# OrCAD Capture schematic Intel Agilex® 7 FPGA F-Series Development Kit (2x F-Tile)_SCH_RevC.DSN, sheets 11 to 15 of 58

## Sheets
11 PG11 AGX SDM: size C
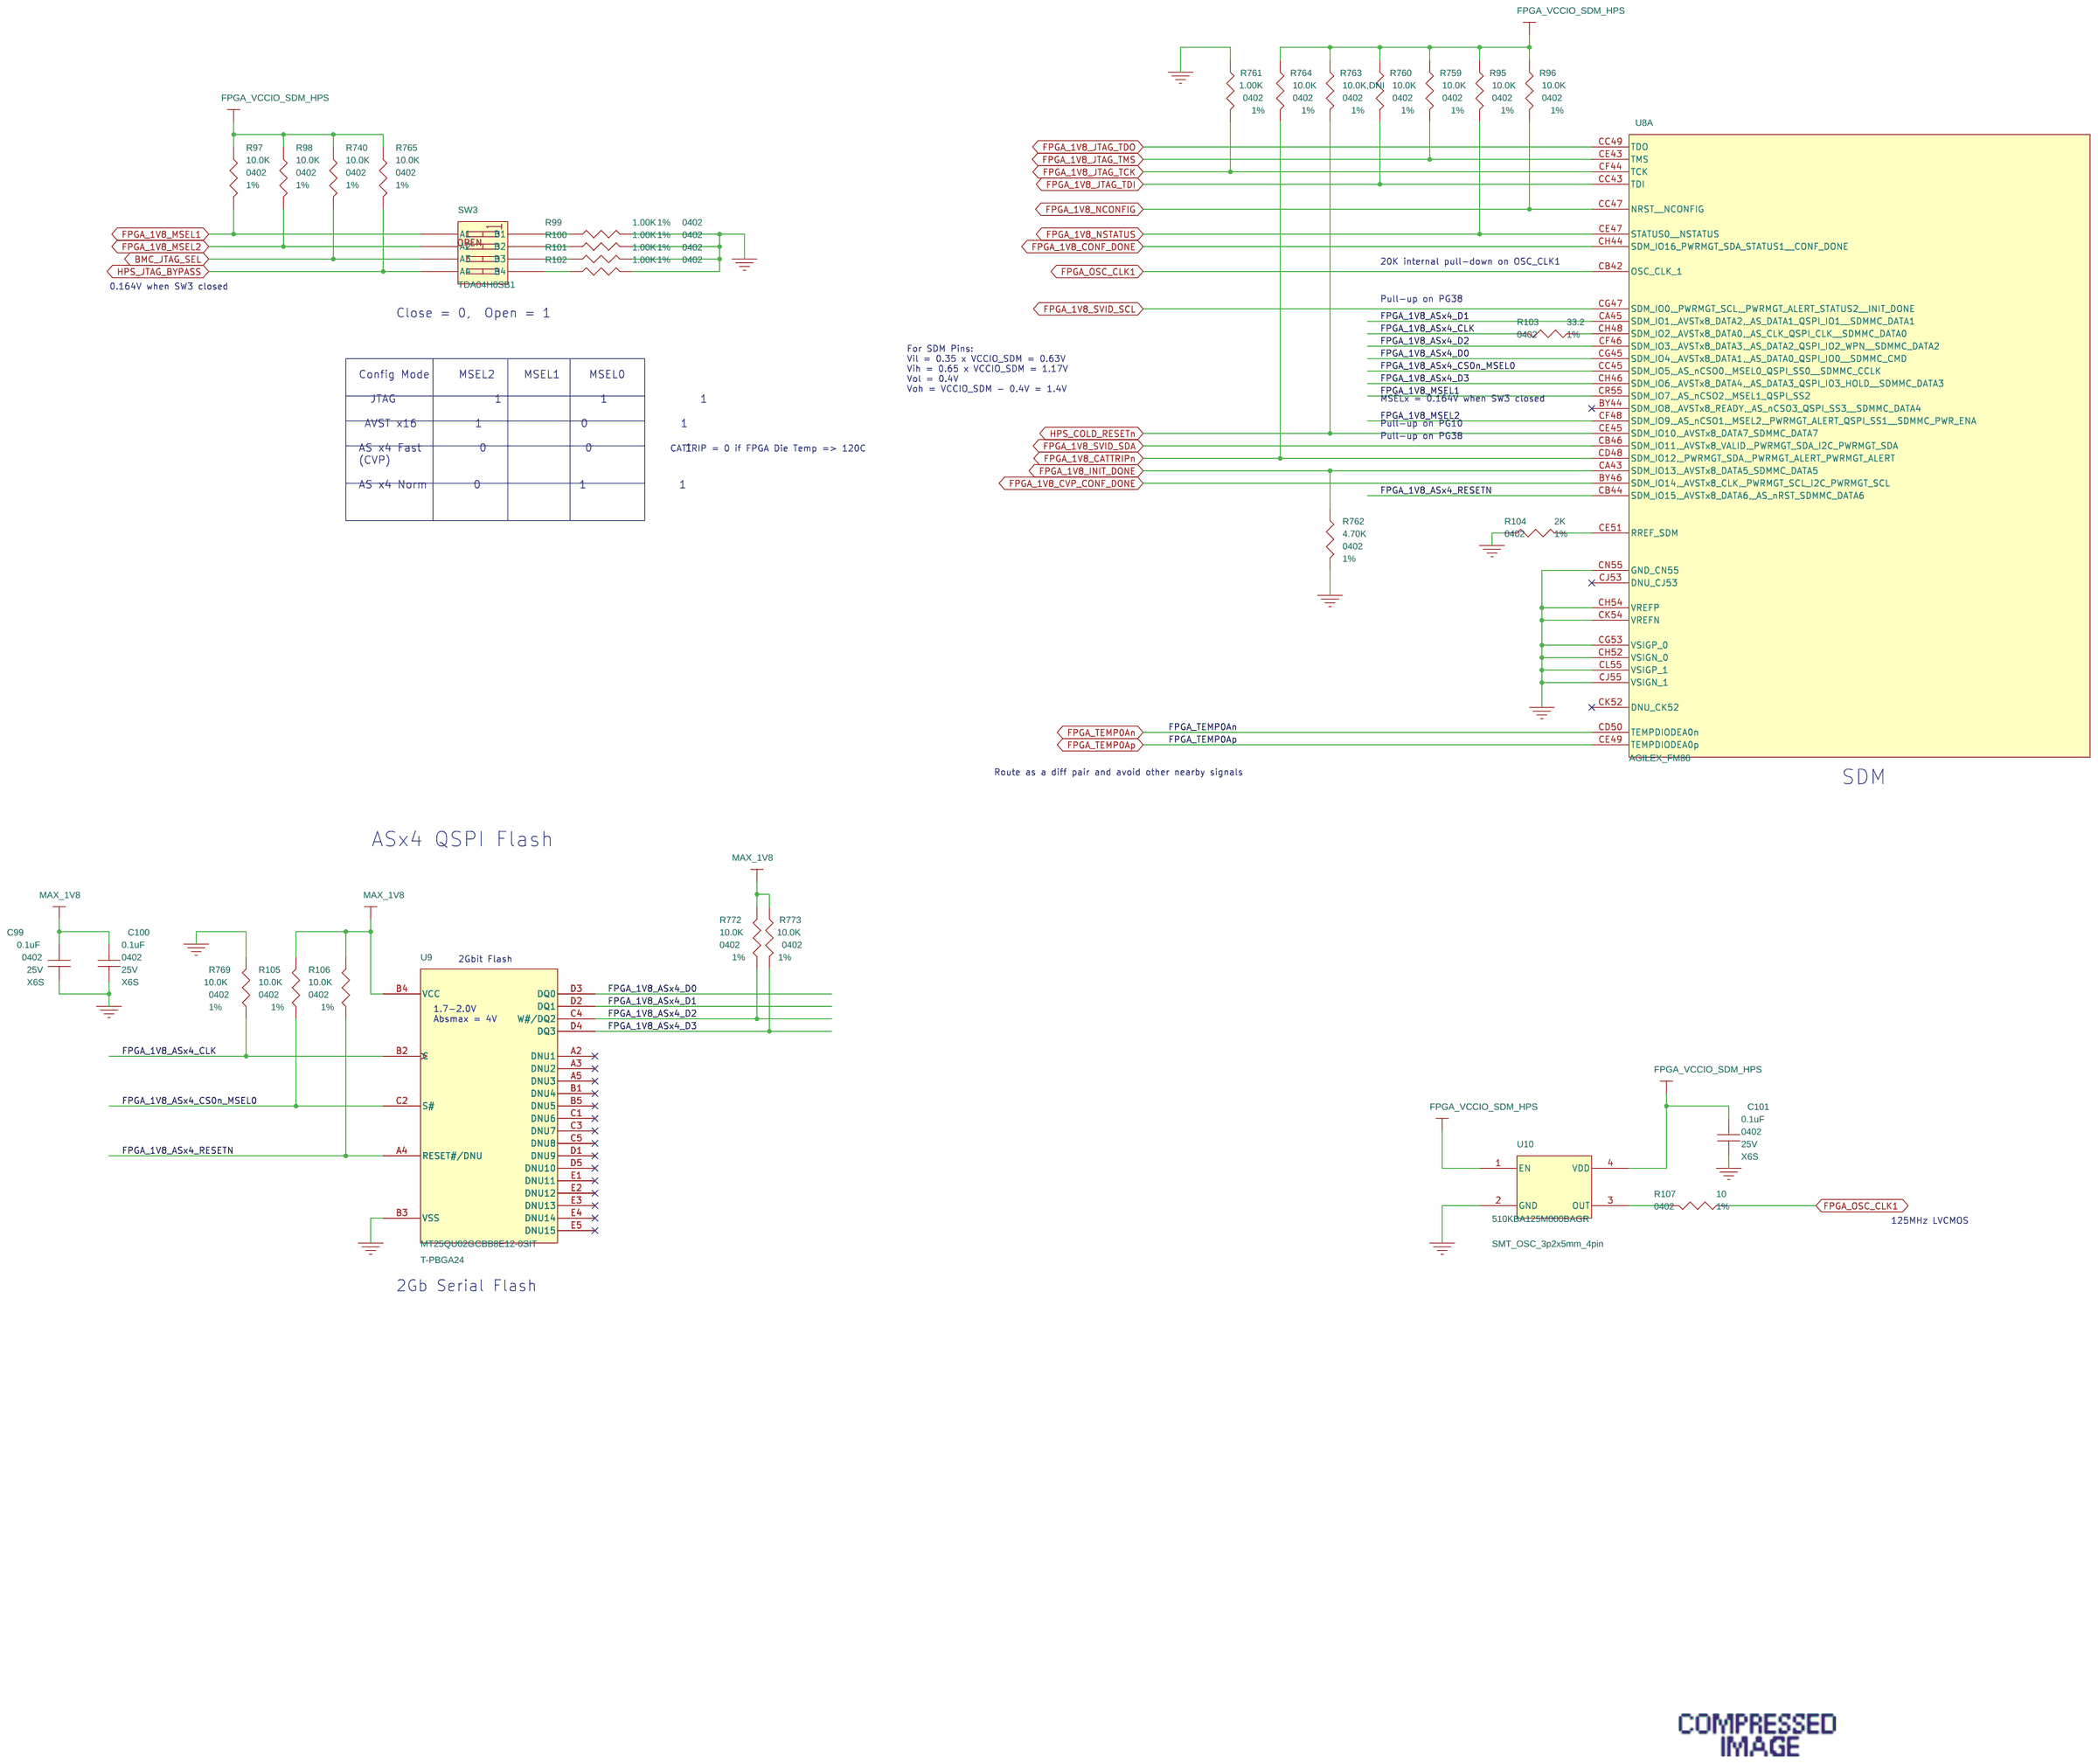
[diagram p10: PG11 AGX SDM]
12 PG12 AGX BANK 2C - DDR4 DIMM1: size C
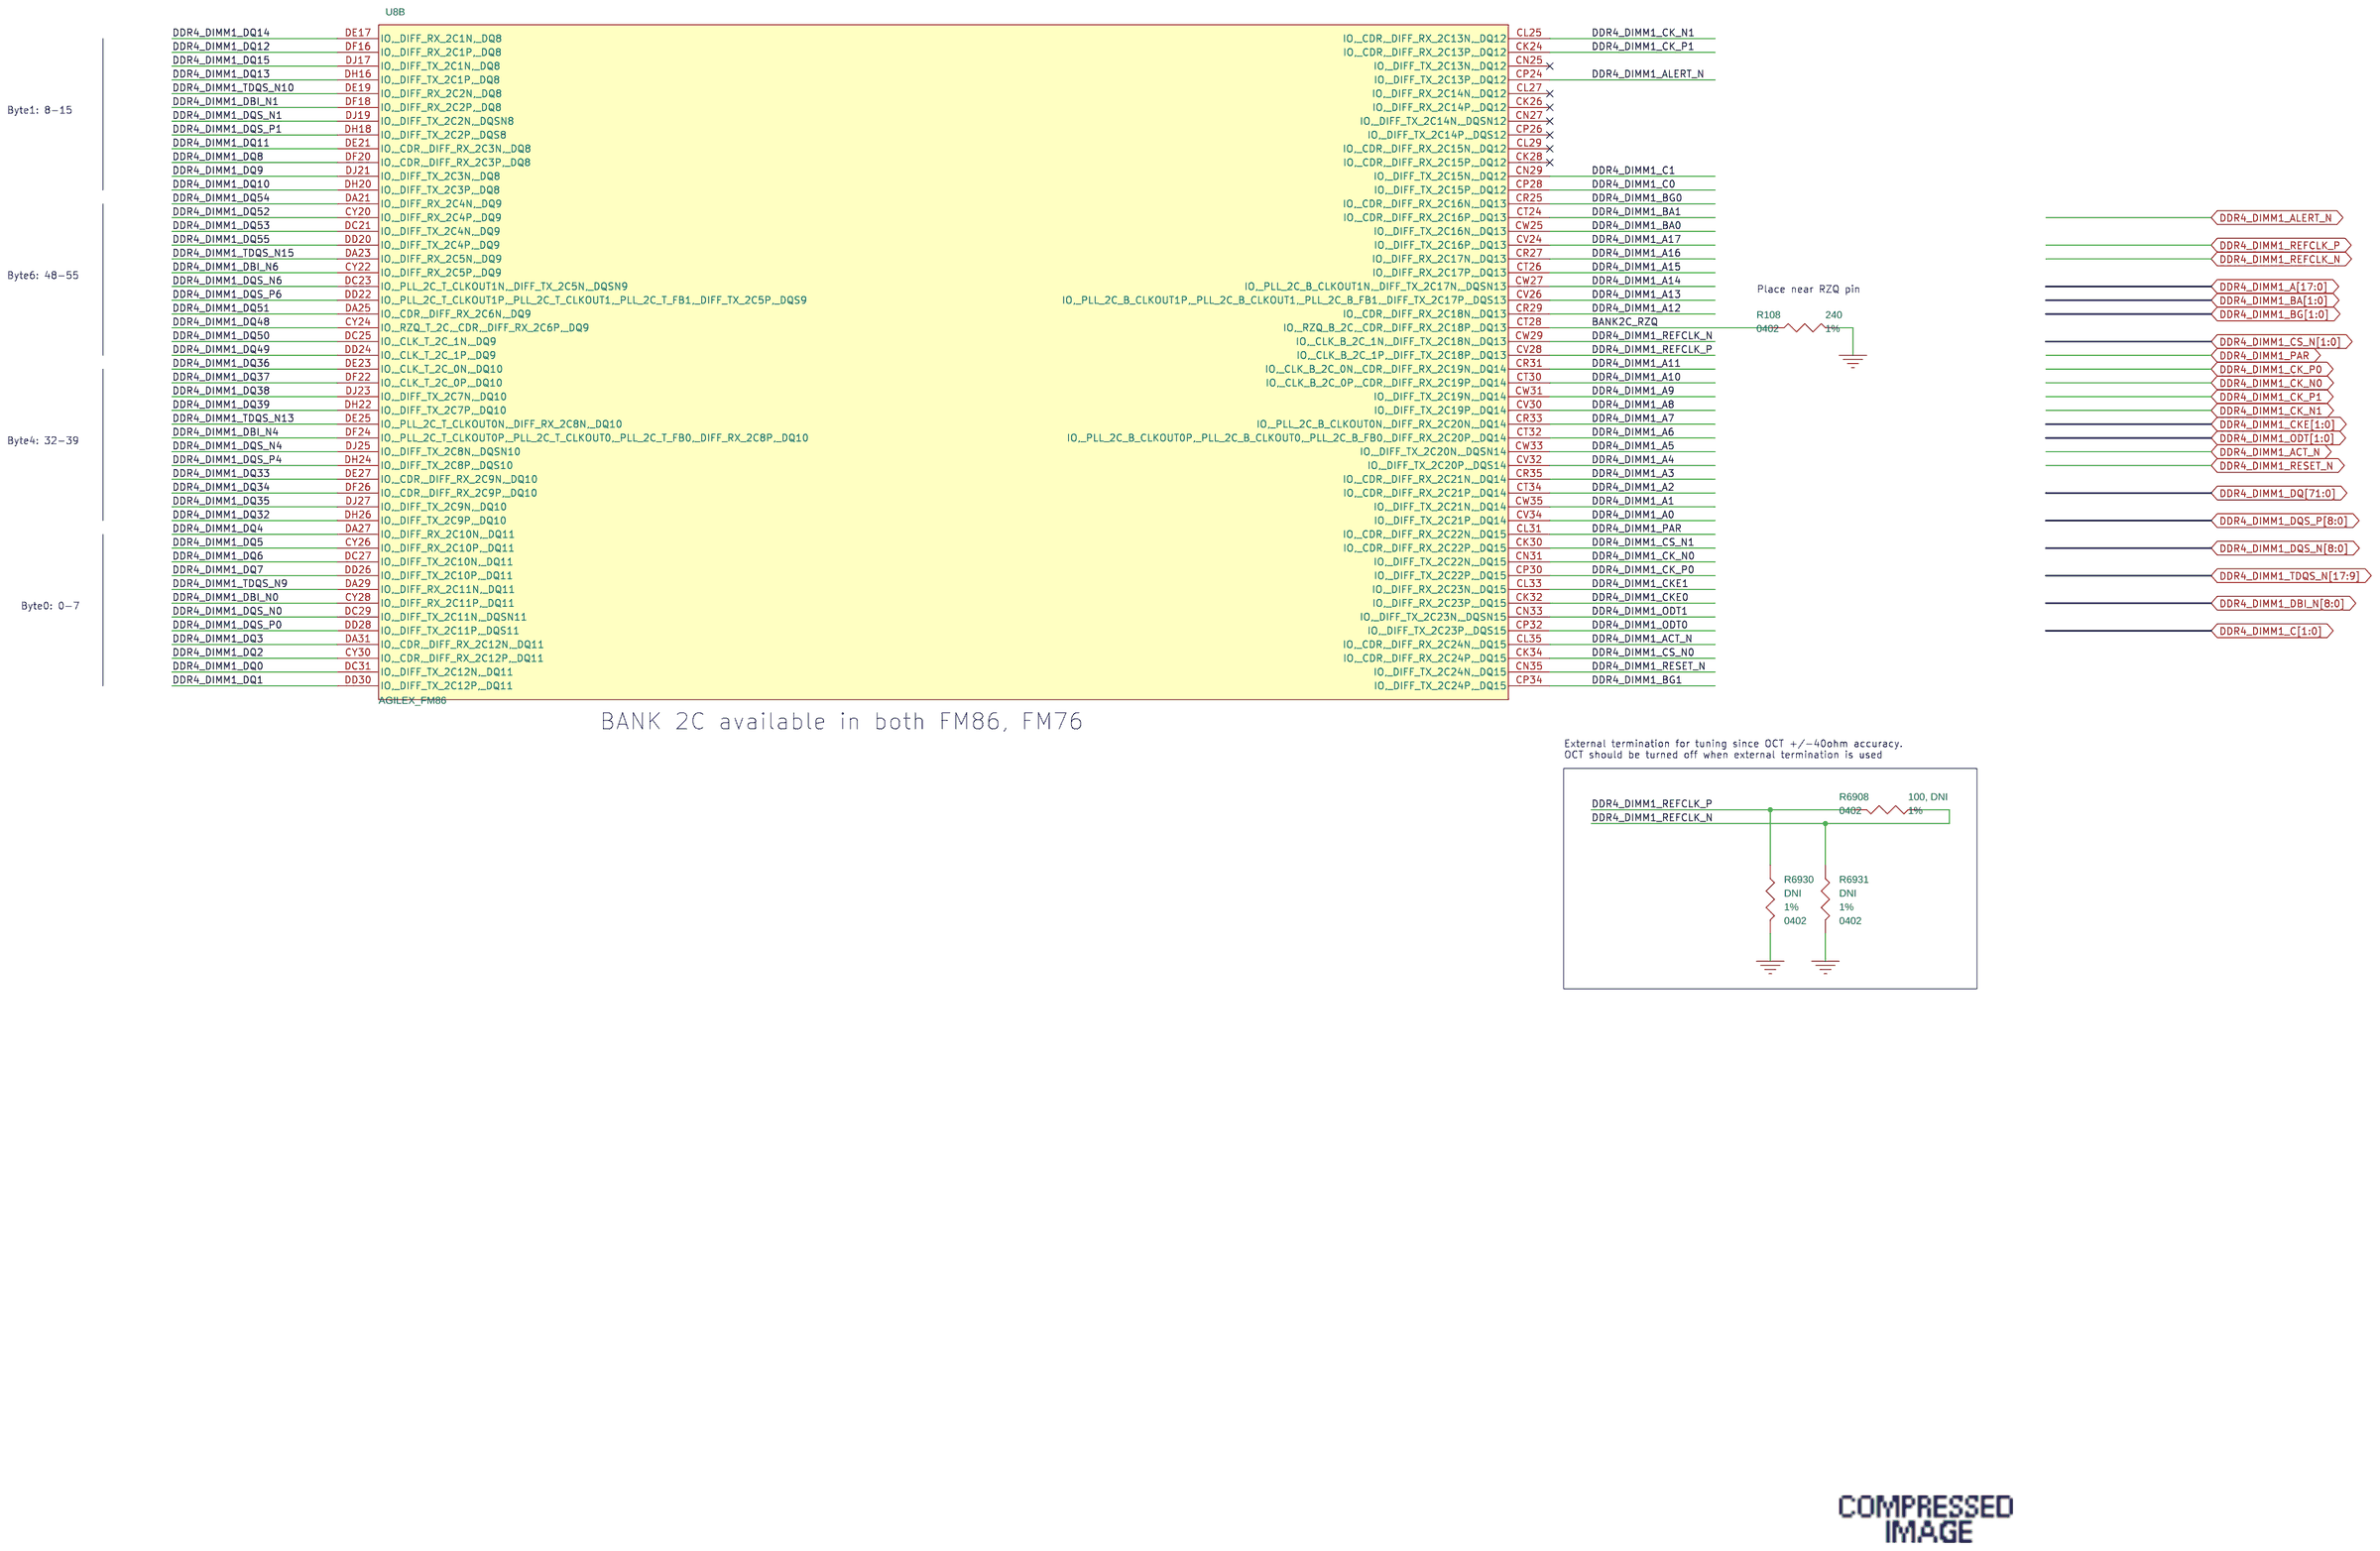
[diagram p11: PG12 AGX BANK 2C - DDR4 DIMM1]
13 PG13 AGX BANK 2D - DDR4 DIMM1: size C
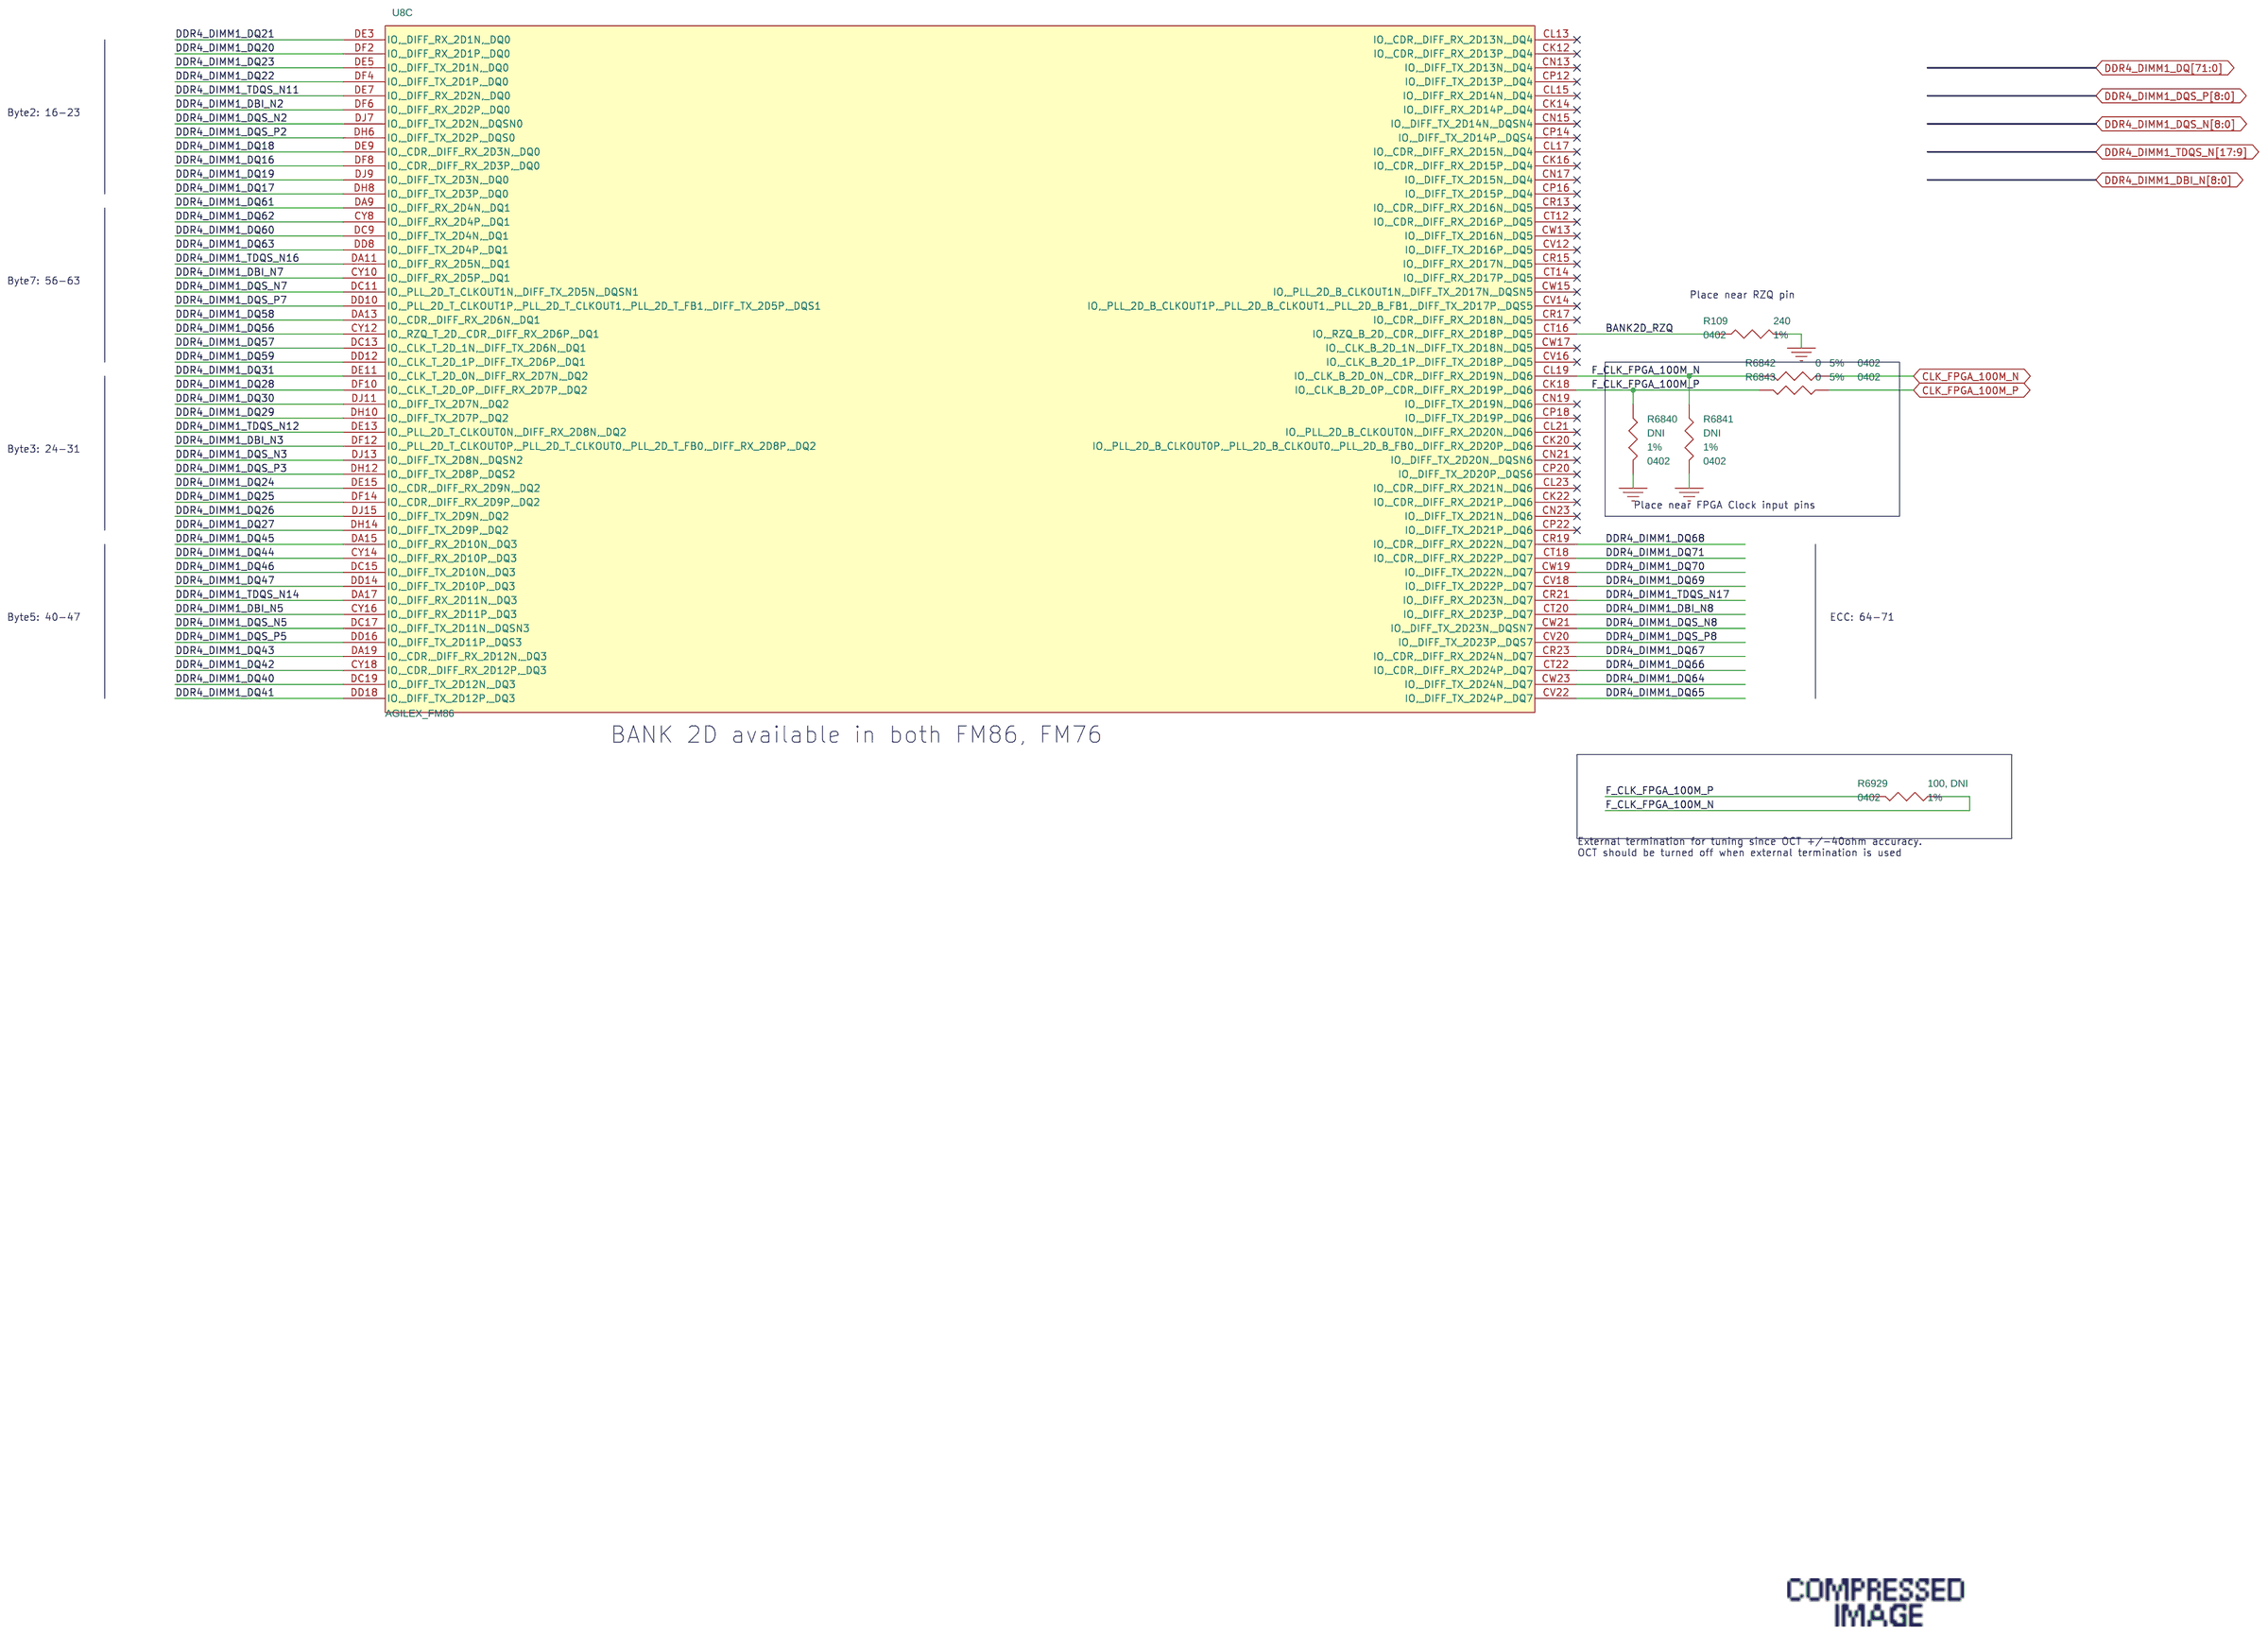
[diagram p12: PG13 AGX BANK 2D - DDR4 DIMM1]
14 PG14 AGX BANK 2E - DDR4 DIMM2: size C
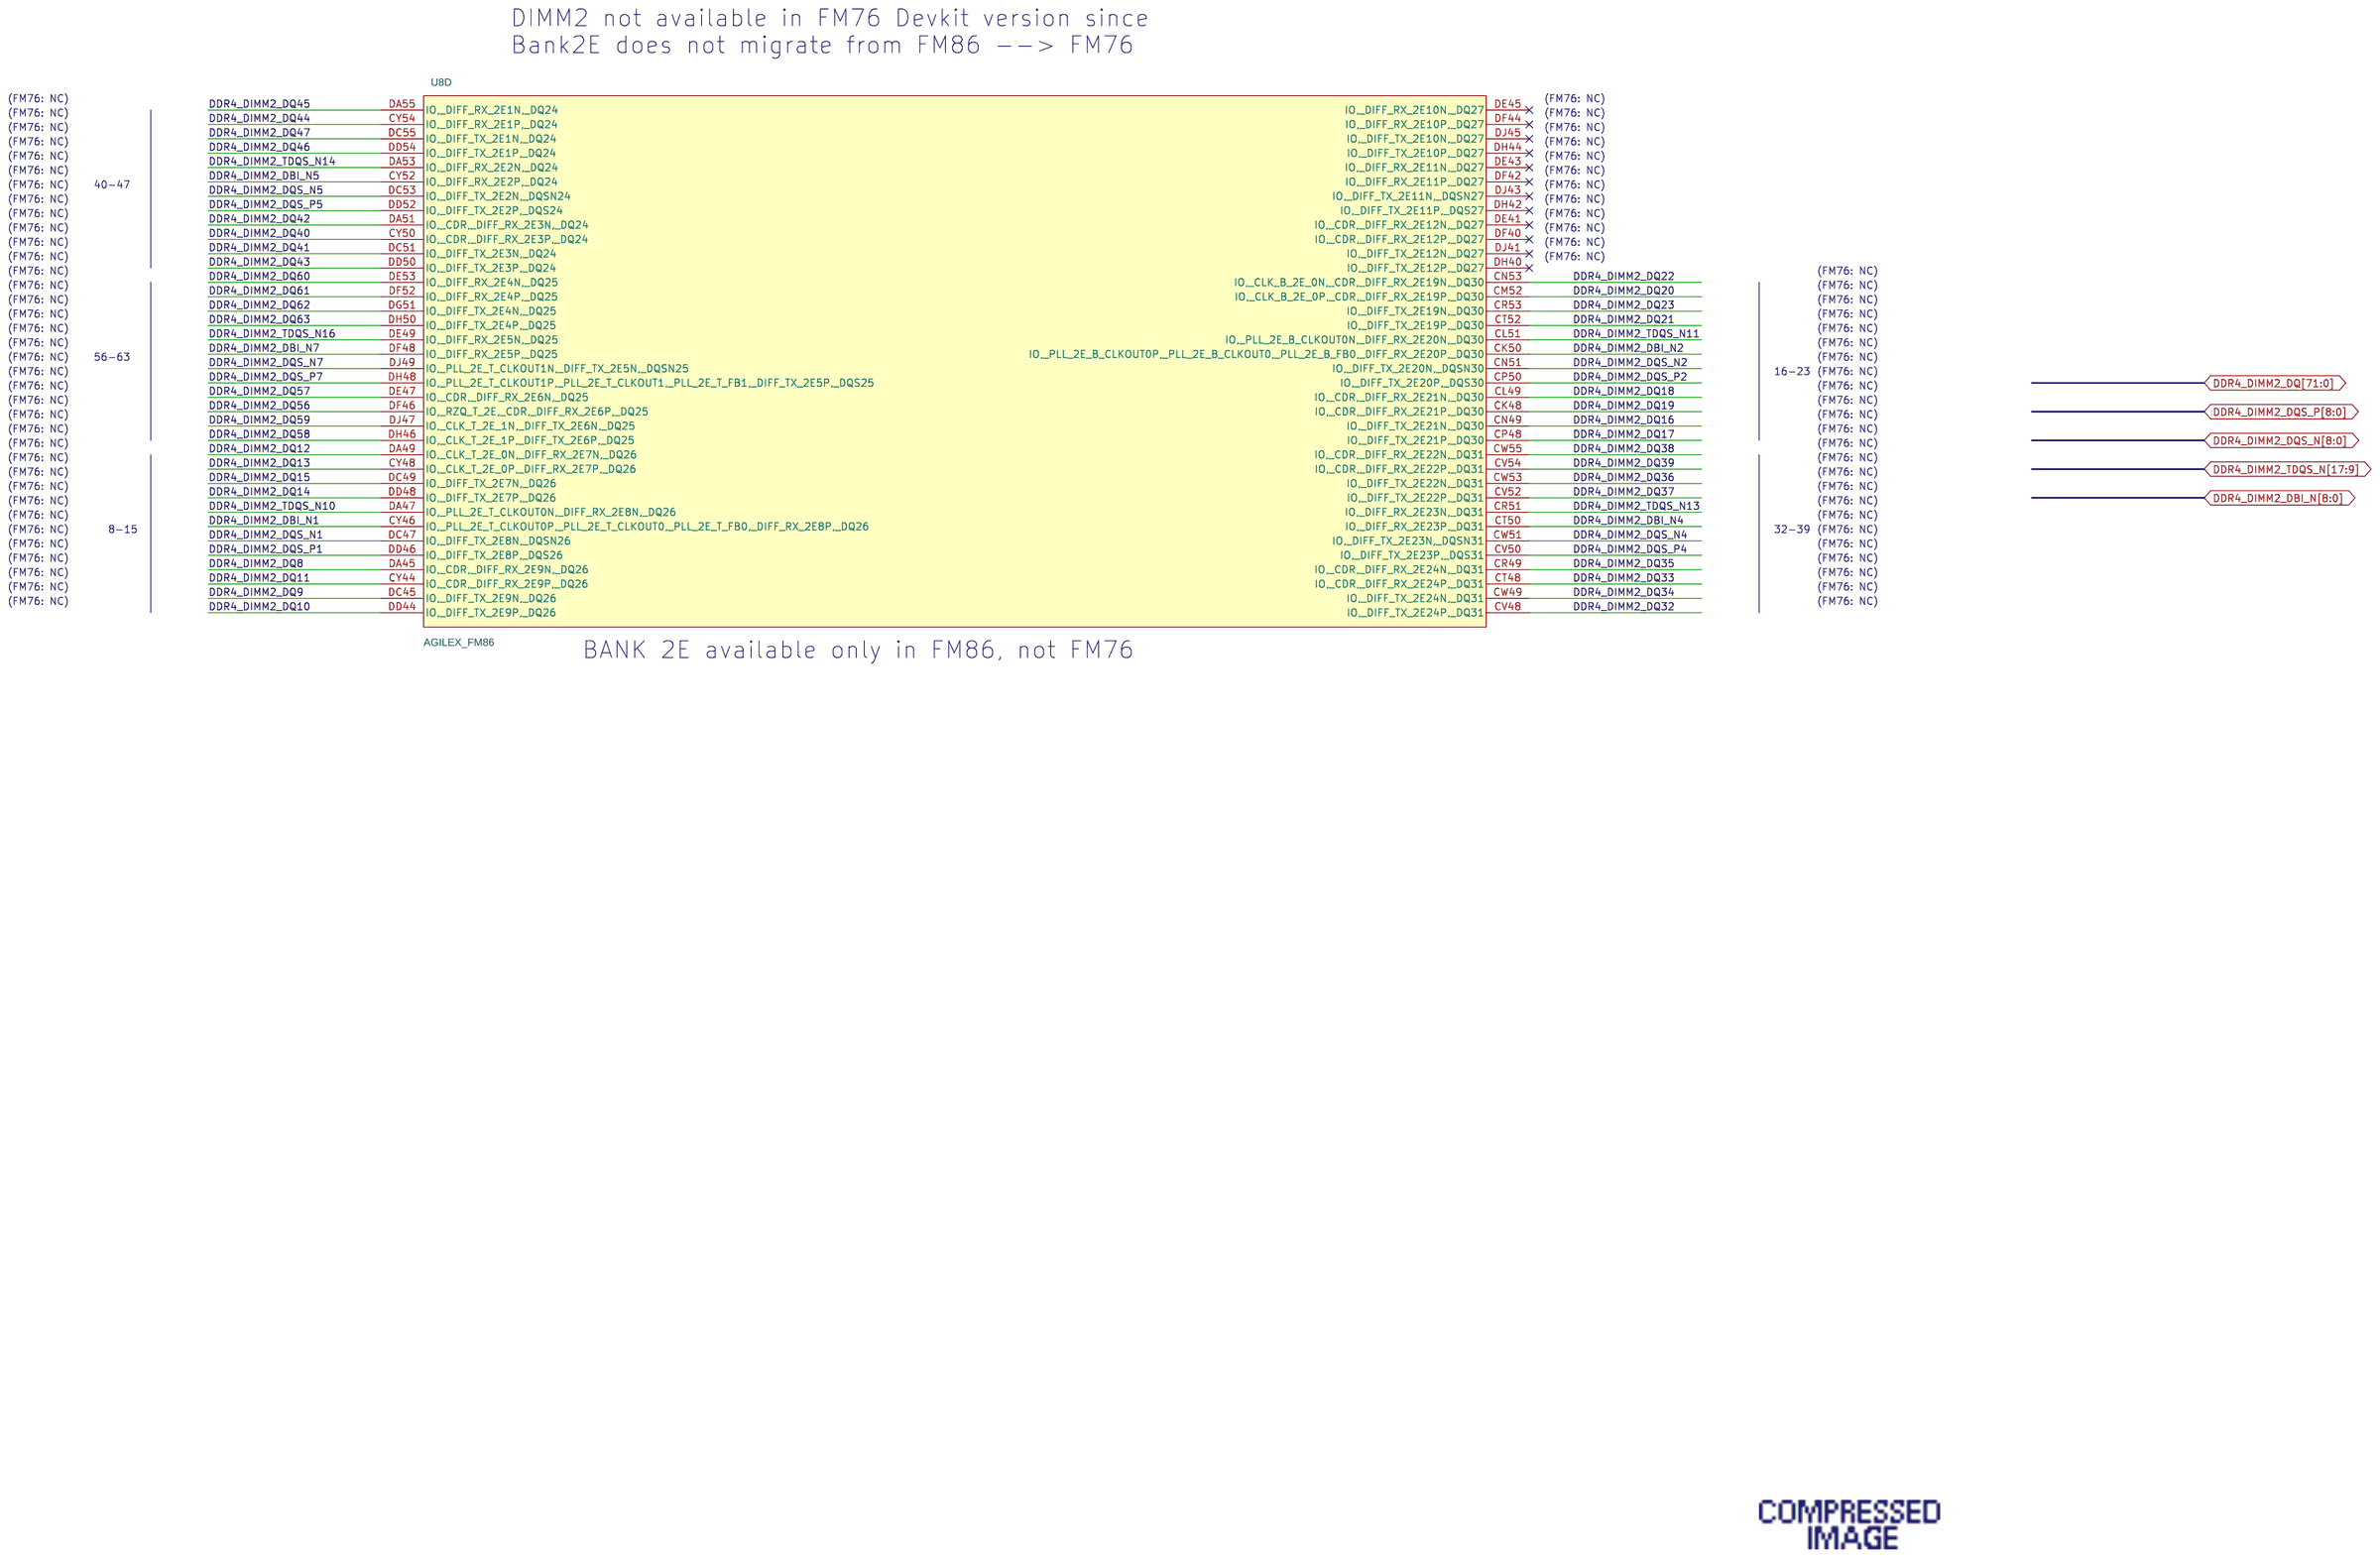
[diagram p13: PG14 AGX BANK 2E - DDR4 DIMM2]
15 PG15 AGX BANK 2F - DDR4 DIMM2: size C
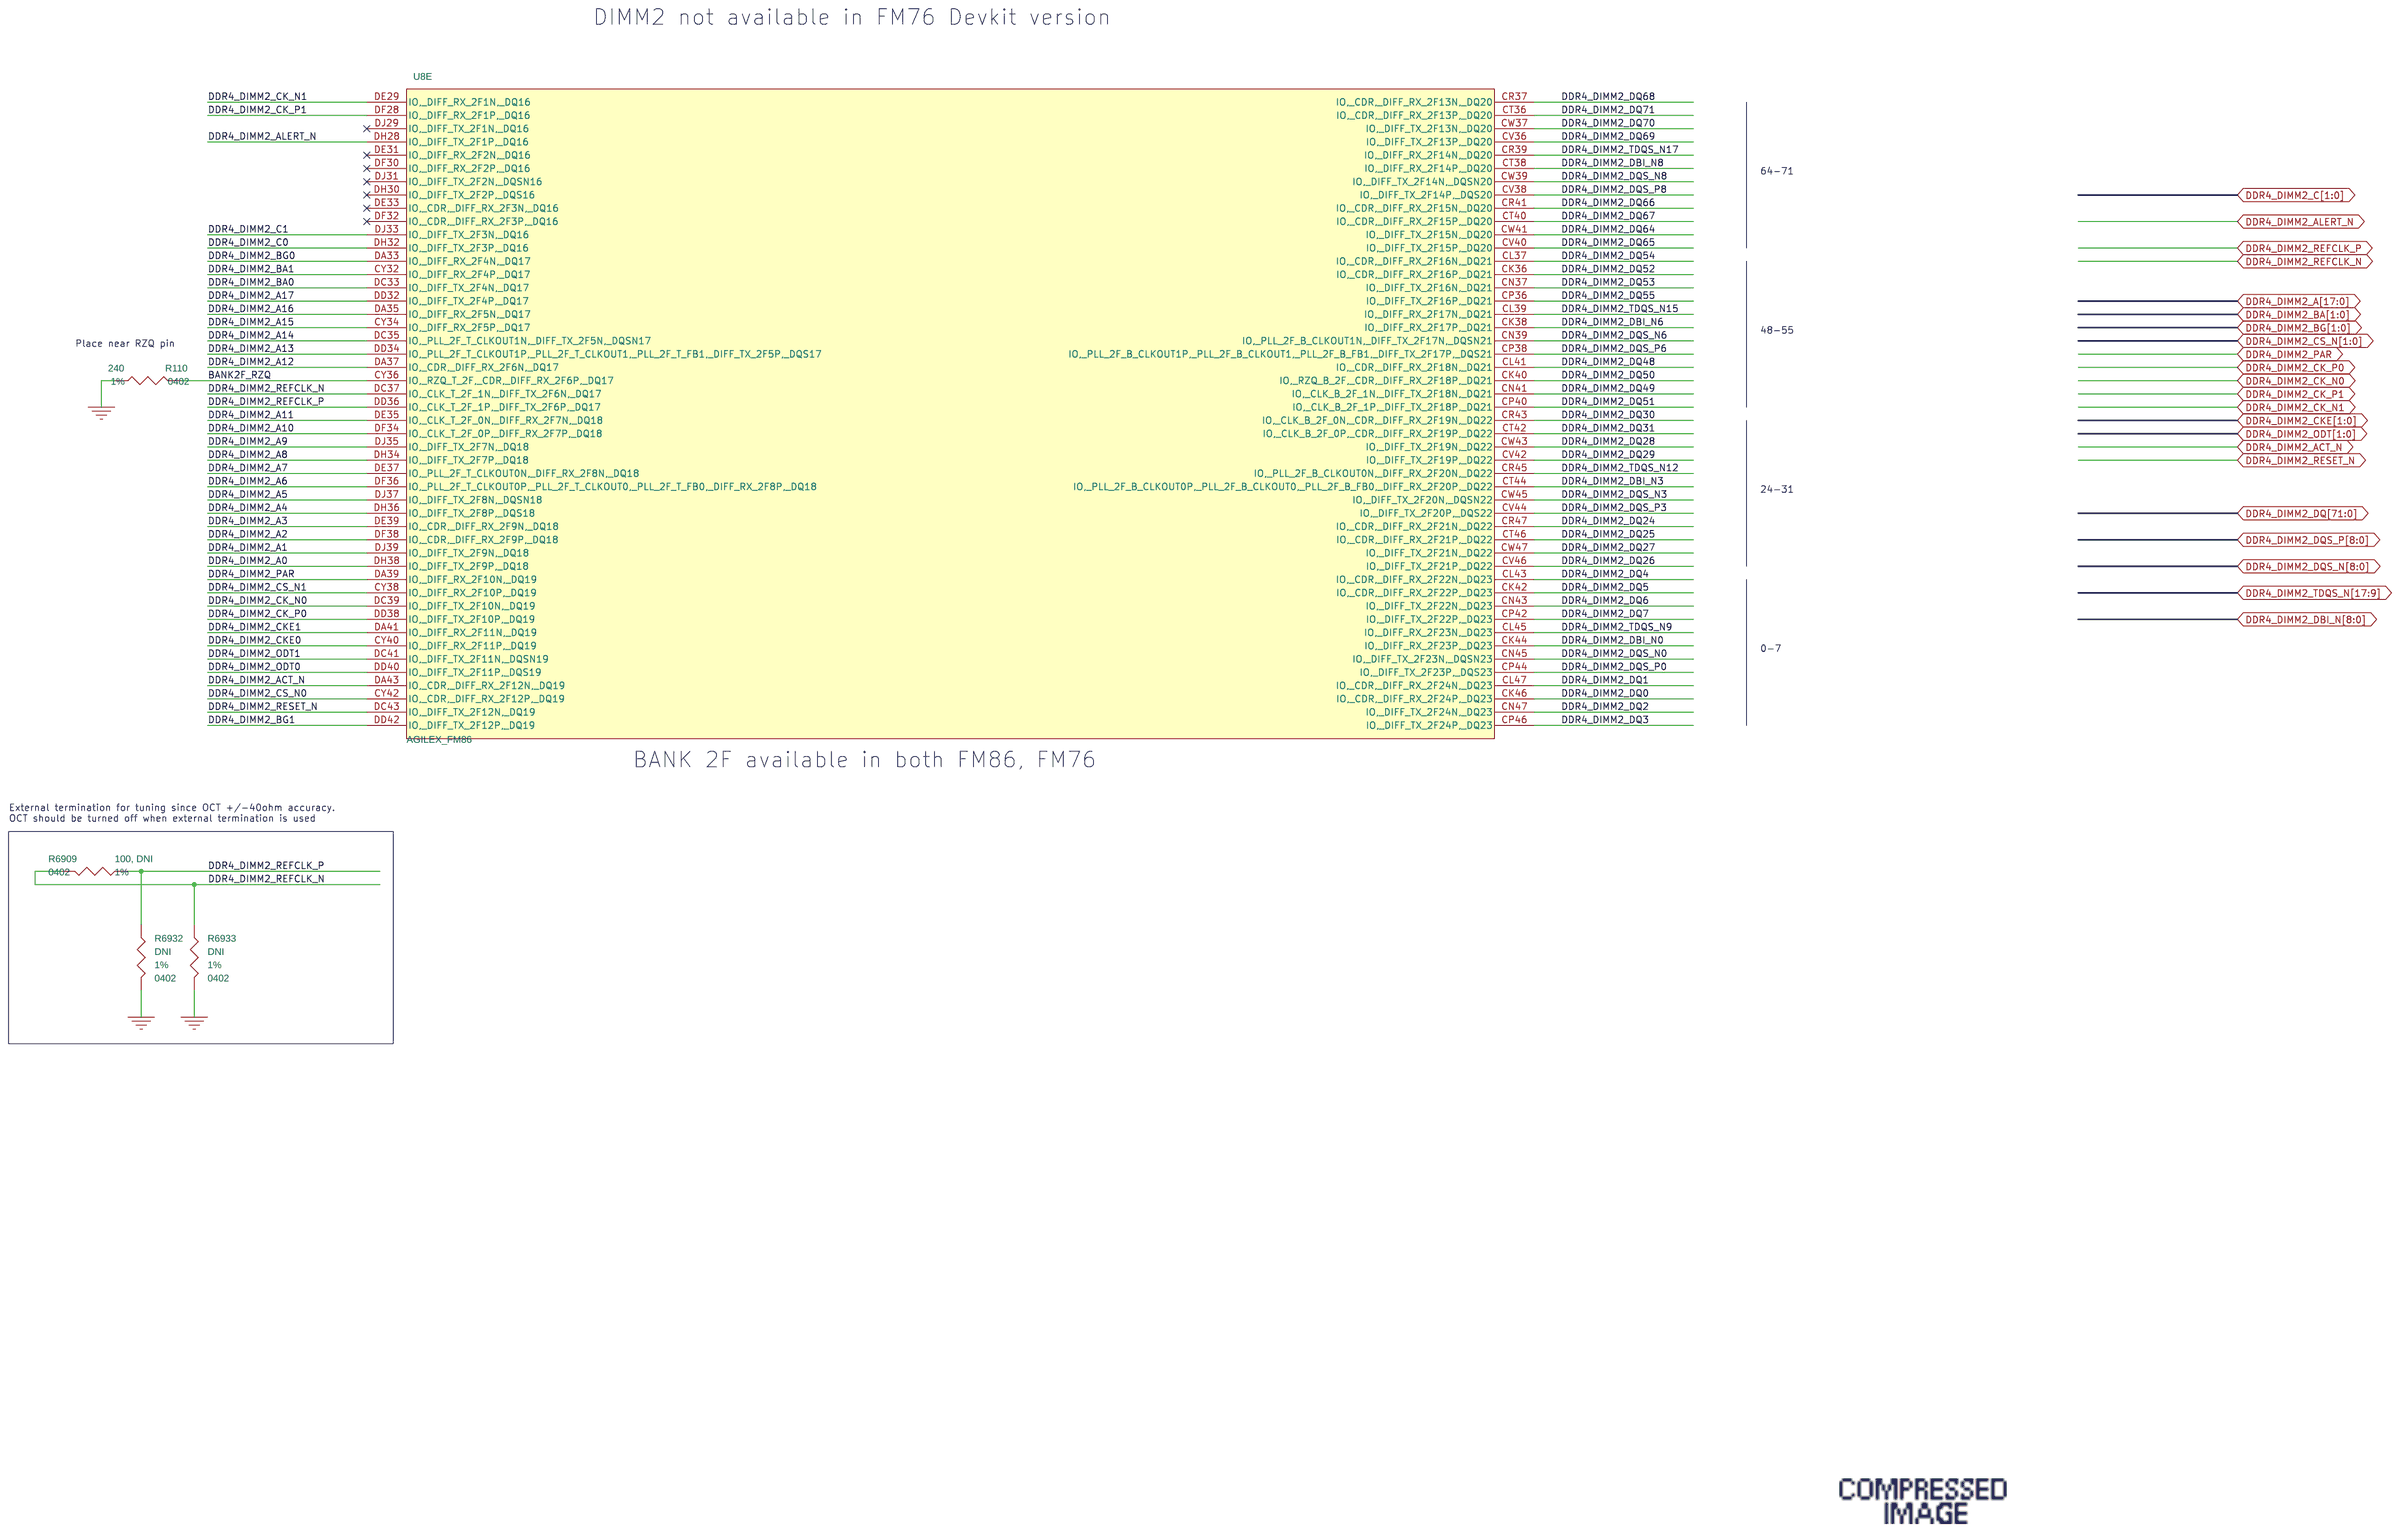
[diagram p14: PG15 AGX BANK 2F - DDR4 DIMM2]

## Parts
sheet PG11 AGX SDM
C99  0.1uF  [0402]
C100  0.1uF  [0402]
C101  0.1uF  [0402]
R95  10.0K  [0402]
R96  10.0K  [0402]
R97  10.0K  [0402]
R98  10.0K  [0402]
R99  1.00K  [0402]
R100  1.00K  [0402]
R101  1.00K  [0402]
R102  1.00K  [0402]
R103  33.2  [0402]
R104  2K  [0402]
R105  10.0K  [0402]
R106  10.0K  [0402]
R107  10  [0402]
R740  10.0K  [0402]
R759  10.0K  [0402]
R760  10.0K  [0402]
R761  1.00K  [0402]
R762  4.70K  [0402]
R763  10.0K,DNI  [0402]
R764  10.0K  [0402]
R765  10.0K  [0402]
R769  10.0K  [0402]
R772  10.0K  [0402]
R773  10.0K  [0402]
SW3  TDA04H0SB1  [DIPSWITCH_SMT_QUAD]
U9  MT25QU02GCBB8E12-0SIT  [T-PBGA24]
U10  510KBA125M000BAGR  [SMT_OSC_3p2x5mm_4pin]
sheet PG12 AGX BANK 2C - DDR4 DIMM1
R108  240  [0402]
R6908  100, DNI  [0402]
R6930  DNI  [0402]
R6931  DNI  [0402]
sheet PG13 AGX BANK 2D - DDR4 DIMM1
R109  240  [0402]
R6840  DNI  [0402]
R6841  DNI  [0402]
R6842  0  [0402]
R6843  0  [0402]
R6929  100, DNI  [0402]
sheet PG14 AGX BANK 2E - DDR4 DIMM2
U8  AGILEX_FM86  [FBGA-2340]  (sections A,B,C,D,E,F,G,H,I,J,K,L,M,N,O,P,Q,R,S,T,U,V,W)
sheet PG15 AGX BANK 2F - DDR4 DIMM2
R110  240  [0402]
R6909  100, DNI  [0402]
R6932  DNI  [0402]
R6933  DNI  [0402]

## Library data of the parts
C99-C101 = CAP: CAP CER 0.1UF 25V X6S 0402; Dielectric: X6S; IPN: K19434-001; Item Num: K19434-001; LIFECYCLE_PHASE: Active; Lead Free Status: Lead Free; MFR_LIFECYCLE: Active; Manufacturer: Murata; Manufacturer Part Num: GRM155C81E104KA12D; Num Pins: 2; PART_SUBCLASS: CAPACITORS; Part Class: CAPACITORS; RATED_VOLTAGE: 25V; RoHS Compliant: RoHS Compliant; Temperature Coefficient: X6S; Tolerance: 10%
R95-R98 R105 R106 R740 R759 R760 R764 R765 R769 R772 R773 = RESISTOR: RES,10.0K OHMS,1.0%,1/16W, 0402; AGILE_LINK: http://sj-agile9app/Agile/PLMServlet?action=OpenEmailObject&classid=10000&objid=146548997; Item Num: K28115-001; LIFECYCLE_PHASE: Active; Lead Free Status: Yes; MFR_LIFECYCLE: Active; Manufacturer: Panasonic; Manufacturer Part Num: ERJ-2RKF1002X; Num Pins: 2; PART_SUBCLASS: RESISTORS; POWER: 1/16W; RoHS Compliant: Yes; TOLERANCE: 1%
R99-R102 = RESISTOR: RES,1.00K OHMS,1.0%,1/16W,0402; Item Num: G60609-021; Lead Free Status: Yes; Manufacturer: Panasonic; Manufacturer Part Num: ERJ-2RKF1001X; Num Pins: 2; Part Class: Resistors; Tolerance: 1%
R103 = RESISTOR: RES,33.2 OHMS,1.0%,1/16W,0402; AGILE_LINK: http://sj-agile9app/Agile/PLMServlet?action=OpenEmailObject&classid=10000&objid=146932246; Item Num: J38619-001; LIFECYCLE_PHASE: Active; MFR_LIFECYCLE: Active; Manufacturer: Panasonic; Manufacturer Part Num: ERJ-2RKF33R2X; Num Pins: 2; PART_SUBCLASS: RESISTORS; POWER: 1/16W; RESISTANCE: 10; RoHS Compliant: RoHS Compliant; TOLERANCE: 1%
R104 = RESISTOR: RES SMD 2K OHM 1% 1/16W 0402; Item Num: J43524-001; Lead Free Status: Yes; Manufacturer: Panasonic; Manufacturer Part Num: ERJ-2RKF2001X; Num Pins: 2; Part Class: RESISTORS; Power Rating: 1/16W; RoHS Compliant: Yes; Tolerance: 1%
R107 = RESISTOR: RES, 10 OHM, 1%, 1/16W, 0402; Item Num: A80345-001; LIFECYCLE_PHASE: Active; Lead Free Status: Yes; Manufacturer: Panasonic; Manufacturer Part Num: ERJ-2RKF10R0X; Num Pins: 2; PART_SUBCLASS: RESISTORS; POWER: 1/16W; Part Class: Resistors; RoHS Compliant: Yes; TOLERANCE: 1%
R761 = RESISTOR: RES,1.00K OHMS,1.0%,1/16W,0402; Item Num: G60609-021; Lead Free Status: Yes; Manufacturer: Panasonic; Manufacturer Part Num: ERJ-2RKF1001X; Num Pins: 2; Part Class: Resistors; TOLERANCE: 1%
R762 = RESISTOR: RES,4.70K OHMS,1.0%,1/16W,0402; AGILE_LINK: http://sj-agile9app/Agile/PLMServlet?action=OpenEmailObject&classid=10000&objid=146753272; Item Num: A93548-517; LIFECYCLE_PHASE: Active; Lead Free Status: Yes; MFR_LIFECYCLE: Active; Manufacturer: Vishay; Manufacturer Part Num: CRCW04024K70FKED; Num Pins: 2; PART_SUBCLASS: RESISTORS; POWER: 1/16W; RESISTANCE: 4.7K; RoHS Compliant: Yes; TOLERANCE: 1%
R763 = RESISTOR: RES,10.0K OHMS,1.0%,1/16W, 0402; AGILE_LINK: http://sj-agile9app/Agile/PLMServlet?action=OpenEmailObject&classid=10000&objid=146548997; Item Num: K28115-001; LIFECYCLE_PHASE: Active; Lead Free Status: Yes; MFR_LIFECYCLE: Active; Manufacturer: Panasonic; Manufacturer Part Num: ERJ-2RKF1002X; Num Pins: 2; PART_SUBCLASS: RESISTORS; POWER: 1/16W; RESISTANCE: 10.0K; RoHS Compliant: Yes; TOLERANCE: 1%
SW3 = SPST4: SWITCHES - 4 POS, 8 PIN, Ultra-mini SMT Half-pitch Slider DIP Switch; Item Num: K15518-001; Lead Free Status: Yes; Manufacturer: C & K Components/ITT Industries; Num Pins: 8; Part Class: Switches; Price: 0; RoHS Compliant: Yes; Supplier: 8
U9 = MT25QU01GBBB: IC, 2Gb 1.8V Serial NOR Flash Memory; Item Num: K59819-001; Manufacturer: Micron
U10 = SiLabs_510GBA25M0000BAGR: IC, Crystal Oscillator 125.0000MHz; Item Num: K21783-001; Manufacturer: SiLabs
R108-R110 = RESISTOR: RES - 240 OHM, 1/16W, 1%, 0402 SMD; Item Num: K15783-001; LIFECYCLE_PHASE: Active; Lead Free Status: Yes; MFR_LIFECYCLE: Active; Manufacturer: Panasonic; Manufacturer Part Num: ERJ-2RKF2400X; Num Pins: 2; PART_SUBCLASS: RESISTORS; RoHS Compliant: Yes; Tolerance: 1%
R6840 R6841 R6908 R6909 R6929-R6933 = RESISTOR: RES,100 OHMS,1.0%,1/16W,0402; Item Num: A36092-043; Lead Free Status: Yes; Manufacturer: Yageo; Manufacturer Part Num: RC0402FR-07100RL; Num Pins: 2; Part Class: Resistors; Price: 0; RoHS Compliant: Yes; Tolerance: 1%
R6842 R6843 = RES_0_OHM_5%_1_16W_0402_SMD: Item Num: A93549-001; Manufacturer: Yageo; Manufacturer Part Num: RC0402JR-070RL; Num Pins: 2; RoHS Compliant: Yes; Tolerance: 5%
U8 = AGILEX_FM86: IC, FPGA, AGILEX FM86, FBGA2340; Manufacturer: Intel; Manufacturer Part Num: AGFB027R24C2E2VR0

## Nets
GND: C99.1 C100.1 C101.1 R99.1 R100.1 R101.1 R102.1 R104.1 R108.1 R109.1 R110.1 R761.1 R762.1 R769.2 R6840.2 R6841.2 R6930.2 R6931.2 R6932.2 R6933.2 U8.CG53(VSIGP_0) U8.CH52(VSIGN_0) U8.CH54(VREFP) U8.CJ55(VSIGN_1) U8.CK54(VREFN) U8.CL55(VSIGP_1) U8.CN55(GND) U9.B3(VSS) U10.2(GND) ; also on sheet 8 9 10 16 19 20 21 22 23 24 25 26 27 28 29 30 31 32 33 34 35 36 37 38 39 40 41 42 43 44 45 46 47 48 49 50 51 52 53 54 55 56 58
BANK2C_RZQ: R108.2 U8.CT28(IO,_RZQ_B_2C,_CDR,_DIFF_RX_2C18P,_DQ13)
BANK2D_RZQ: R109.2 U8.CT16(IO,_RZQ_B_2D,_CDR,_DIFF_RX_2D18P,_DQ5)
BANK2F_RZQ: R110.2 U8.CY36(IO,_RZQ_T_2F,_CDR,_DIFF_RX_2F6P,_DQ17)
BMC_JTAG_SEL: R740.1 SW3.3(A3) ; also on sheet 10
CLK_FPGA_100M_N: R6842.1 ; also on sheet 32
CLK_FPGA_100M_P: R6843.1 ; also on sheet 32
DDR4_DIMM1_A0: U8.CV34(IO,_DIFF_TX_2C21P,_DQ14) ; also on sheet 55
DDR4_DIMM1_A1: U8.CW35(IO,_DIFF_TX_2C21N,_DQ14) ; also on sheet 55
DDR4_DIMM1_A2: U8.CT34(IO,_CDR,_DIFF_RX_2C21P,_DQ14) ; also on sheet 55
DDR4_DIMM1_A3: U8.CR35(IO,_CDR,_DIFF_RX_2C21N,_DQ14) ; also on sheet 55
DDR4_DIMM1_A4: U8.CV32(IO,_DIFF_TX_2C20P,_DQS14) ; also on sheet 55
DDR4_DIMM1_A5: U8.CW33(IO,_DIFF_TX_2C20N,_DQSN14) ; also on sheet 55
DDR4_DIMM1_A6: U8.CT32(IO,_PLL_2C_B_CLKOUT0P,_PLL_2C_B_CLKOUT0,_PLL_2C_B_FB0,_DIFF_RX_2C20P,_DQ14) ; also on sheet 55
DDR4_DIMM1_A7: U8.CR33(IO,_PLL_2C_B_CLKOUT0N,_DIFF_RX_2C20N,_DQ14) ; also on sheet 55
DDR4_DIMM1_A8: U8.CV30(IO,_DIFF_TX_2C19P,_DQ14) ; also on sheet 55
DDR4_DIMM1_A9: U8.CW31(IO,_DIFF_TX_2C19N,_DQ14) ; also on sheet 55
DDR4_DIMM1_A10: U8.CT30(IO,_CLK_B_2C_0P,_CDR,_DIFF_RX_2C19P,_DQ14) ; also on sheet 55
DDR4_DIMM1_A11: U8.CR31(IO,_CLK_B_2C_0N,_CDR,_DIFF_RX_2C19N,_DQ14) ; also on sheet 55
DDR4_DIMM1_A12: U8.CR29(IO,_CDR,_DIFF_RX_2C18N,_DQ13) ; also on sheet 55
DDR4_DIMM1_A13: U8.CV26(IO,_PLL_2C_B_CLKOUT1P,_PLL_2C_B_CLKOUT1,_PLL_2C_B_FB1,_DIFF_TX_2C17P,_DQS13) ; also on sheet 55
DDR4_DIMM1_A14: U8.CW27(IO,_PLL_2C_B_CLKOUT1N,_DIFF_TX_2C17N,_DQSN13) ; also on sheet 55
DDR4_DIMM1_A15: U8.CT26(IO,_DIFF_RX_2C17P,_DQ13) ; also on sheet 55
DDR4_DIMM1_A16: U8.CR27(IO,_DIFF_RX_2C17N,_DQ13) ; also on sheet 55
DDR4_DIMM1_A17: U8.CV24(IO,_DIFF_TX_2C16P,_DQ13) ; also on sheet 55
DDR4_DIMM1_ACT_N: U8.CL35(IO,_CDR,_DIFF_RX_2C24N,_DQ15) ; also on sheet 55
DDR4_DIMM1_ALERT_N: U8.CP24(IO,_DIFF_TX_2C13P,_DQ12) ; also on sheet 55
DDR4_DIMM1_BA0: U8.CW25(IO,_DIFF_TX_2C16N,_DQ13) ; also on sheet 55
DDR4_DIMM1_BA1: U8.CT24(IO,_CDR,_DIFF_RX_2C16P,_DQ13) ; also on sheet 55
DDR4_DIMM1_BG0: U8.CR25(IO,_CDR,_DIFF_RX_2C16N,_DQ13) ; also on sheet 55
DDR4_DIMM1_BG1: U8.CP34(IO,_DIFF_TX_2C24P,_DQ15) ; also on sheet 55
DDR4_DIMM1_C0: U8.CP28(IO,_DIFF_TX_2C15P,_DQ12) ; also on sheet 55
DDR4_DIMM1_C1: U8.CN29(IO,_DIFF_TX_2C15N,_DQ12) ; also on sheet 55
DDR4_DIMM1_CK_N0: U8.CN31(IO,_DIFF_TX_2C22N,_DQ15) ; also on sheet 55
DDR4_DIMM1_CK_N1: U8.CL25(IO,_CDR,_DIFF_RX_2C13N,_DQ12) ; also on sheet 55
DDR4_DIMM1_CK_P0: U8.CP30(IO,_DIFF_TX_2C22P,_DQ15) ; also on sheet 55
DDR4_DIMM1_CK_P1: U8.CK24(IO,_CDR,_DIFF_RX_2C13P,_DQ12) ; also on sheet 55
DDR4_DIMM1_CKE0: U8.CK32(IO,_DIFF_RX_2C23P,_DQ15) ; also on sheet 55
DDR4_DIMM1_CKE1: U8.CL33(IO,_DIFF_RX_2C23N,_DQ15) ; also on sheet 55
DDR4_DIMM1_CS_N0: U8.CK34(IO,_CDR,_DIFF_RX_2C24P,_DQ15) ; also on sheet 55
DDR4_DIMM1_CS_N1: U8.CK30(IO,_CDR,_DIFF_RX_2C22P,_DQ15) ; also on sheet 55
DDR4_DIMM1_DBI_N0: U8.CY28(IO,_DIFF_RX_2C11P,_DQ11) ; also on sheet 55
DDR4_DIMM1_DBI_N1: U8.DF18(IO,_DIFF_RX_2C2P,_DQ8) ; also on sheet 55
DDR4_DIMM1_DBI_N2: U8.DF6(IO,_DIFF_RX_2D2P,_DQ0) ; also on sheet 55
DDR4_DIMM1_DBI_N3: U8.DF12(IO,_PLL_2D_T_CLKOUT0P,_PLL_2D_T_CLKOUT0,_PLL_2D_T_FB0,_DIFF_RX_2D8P,_DQ2) ; also on sheet 55
DDR4_DIMM1_DBI_N4: U8.DF24(IO,_PLL_2C_T_CLKOUT0P,_PLL_2C_T_CLKOUT0,_PLL_2C_T_FB0,_DIFF_RX_2C8P,_DQ10) ; also on sheet 55
DDR4_DIMM1_DBI_N5: U8.CY16(IO,_DIFF_RX_2D11P,_DQ3) ; also on sheet 55
DDR4_DIMM1_DBI_N6: U8.CY22(IO,_DIFF_RX_2C5P,_DQ9) ; also on sheet 55
DDR4_DIMM1_DBI_N7: U8.CY10(IO,_DIFF_RX_2D5P,_DQ1) ; also on sheet 55
DDR4_DIMM1_DBI_N8: U8.CT20(IO,_DIFF_RX_2D23P,_DQ7) ; also on sheet 55
DDR4_DIMM1_DQ0: U8.DC31(IO,_DIFF_TX_2C12N,_DQ11) ; also on sheet 55
DDR4_DIMM1_DQ1: U8.DD30(IO,_DIFF_TX_2C12P,_DQ11) ; also on sheet 55
DDR4_DIMM1_DQ2: U8.CY30(IO,_CDR,_DIFF_RX_2C12P,_DQ11) ; also on sheet 55
DDR4_DIMM1_DQ3: U8.DA31(IO,_CDR,_DIFF_RX_2C12N,_DQ11) ; also on sheet 55
DDR4_DIMM1_DQ4: U8.DA27(IO,_DIFF_RX_2C10N,_DQ11) ; also on sheet 55
DDR4_DIMM1_DQ5: U8.CY26(IO,_DIFF_RX_2C10P,_DQ11) ; also on sheet 55
DDR4_DIMM1_DQ6: U8.DC27(IO,_DIFF_TX_2C10N,_DQ11) ; also on sheet 55
DDR4_DIMM1_DQ7: U8.DD26(IO,_DIFF_TX_2C10P,_DQ11) ; also on sheet 55
DDR4_DIMM1_DQ8: U8.DF20(IO,_CDR,_DIFF_RX_2C3P,_DQ8) ; also on sheet 55
DDR4_DIMM1_DQ9: U8.DJ21(IO,_DIFF_TX_2C3N,_DQ8) ; also on sheet 55
DDR4_DIMM1_DQ10: U8.DH20(IO,_DIFF_TX_2C3P,_DQ8) ; also on sheet 55
DDR4_DIMM1_DQ11: U8.DE21(IO,_CDR,_DIFF_RX_2C3N,_DQ8) ; also on sheet 55
DDR4_DIMM1_DQ12: U8.DF16(IO,_DIFF_RX_2C1P,_DQ8) ; also on sheet 55
DDR4_DIMM1_DQ13: U8.DH16(IO,_DIFF_TX_2C1P,_DQ8) ; also on sheet 55
DDR4_DIMM1_DQ14: U8.DE17(IO,_DIFF_RX_2C1N,_DQ8) ; also on sheet 55
DDR4_DIMM1_DQ15: U8.DJ17(IO,_DIFF_TX_2C1N,_DQ8) ; also on sheet 55
DDR4_DIMM1_DQ16: U8.DF8(IO,_CDR,_DIFF_RX_2D3P,_DQ0) ; also on sheet 55
DDR4_DIMM1_DQ17: U8.DH8(IO,_DIFF_TX_2D3P,_DQ0) ; also on sheet 55
DDR4_DIMM1_DQ18: U8.DE9(IO,_CDR,_DIFF_RX_2D3N,_DQ0) ; also on sheet 55
DDR4_DIMM1_DQ19: U8.DJ9(IO,_DIFF_TX_2D3N,_DQ0) ; also on sheet 55
DDR4_DIMM1_DQ20: U8.DF2(IO,_DIFF_RX_2D1P,_DQ0) ; also on sheet 55
DDR4_DIMM1_DQ21: U8.DE3(IO,_DIFF_RX_2D1N,_DQ0) ; also on sheet 55
DDR4_DIMM1_DQ22: U8.DF4(IO,_DIFF_TX_2D1P,_DQ0) ; also on sheet 55
DDR4_DIMM1_DQ23: U8.DE5(IO,_DIFF_TX_2D1N,_DQ0) ; also on sheet 55
DDR4_DIMM1_DQ24: U8.DE15(IO,_CDR,_DIFF_RX_2D9N,_DQ2) ; also on sheet 55
DDR4_DIMM1_DQ25: U8.DF14(IO,_CDR,_DIFF_RX_2D9P,_DQ2) ; also on sheet 55
DDR4_DIMM1_DQ26: U8.DJ15(IO,_DIFF_TX_2D9N,_DQ2) ; also on sheet 55
DDR4_DIMM1_DQ27: U8.DH14(IO,_DIFF_TX_2D9P,_DQ2) ; also on sheet 55
DDR4_DIMM1_DQ28: U8.DF10(IO,_CLK_T_2D_0P,_DIFF_RX_2D7P,_DQ2) ; also on sheet 55
DDR4_DIMM1_DQ29: U8.DH10(IO,_DIFF_TX_2D7P,_DQ2) ; also on sheet 55
DDR4_DIMM1_DQ30: U8.DJ11(IO,_DIFF_TX_2D7N,_DQ2) ; also on sheet 55
DDR4_DIMM1_DQ31: U8.DE11(IO,_CLK_T_2D_0N,_DIFF_RX_2D7N,_DQ2) ; also on sheet 55
DDR4_DIMM1_DQ32: U8.DH26(IO,_DIFF_TX_2C9P,_DQ10) ; also on sheet 55
DDR4_DIMM1_DQ33: U8.DE27(IO,_CDR,_DIFF_RX_2C9N,_DQ10) ; also on sheet 55
DDR4_DIMM1_DQ34: U8.DF26(IO,_CDR,_DIFF_RX_2C9P,_DQ10) ; also on sheet 55
DDR4_DIMM1_DQ35: U8.DJ27(IO,_DIFF_TX_2C9N,_DQ10) ; also on sheet 55
DDR4_DIMM1_DQ36: U8.DE23(IO,_CLK_T_2C_0N,_DQ10) ; also on sheet 55
DDR4_DIMM1_DQ37: U8.DF22(IO,_CLK_T_2C_0P,_DQ10) ; also on sheet 55
DDR4_DIMM1_DQ38: U8.DJ23(IO,_DIFF_TX_2C7N,_DQ10) ; also on sheet 55
DDR4_DIMM1_DQ39: U8.DH22(IO,_DIFF_TX_2C7P,_DQ10) ; also on sheet 55
DDR4_DIMM1_DQ40: U8.DC19(IO,_DIFF_TX_2D12N,_DQ3) ; also on sheet 55
DDR4_DIMM1_DQ41: U8.DD18(IO,_DIFF_TX_2D12P,_DQ3) ; also on sheet 55
DDR4_DIMM1_DQ42: U8.CY18(IO,_CDR,_DIFF_RX_2D12P,_DQ3) ; also on sheet 55
DDR4_DIMM1_DQ43: U8.DA19(IO,_CDR,_DIFF_RX_2D12N,_DQ3) ; also on sheet 55
DDR4_DIMM1_DQ44: U8.CY14(IO,_DIFF_RX_2D10P,_DQ3) ; also on sheet 55
DDR4_DIMM1_DQ45: U8.DA15(IO,_DIFF_RX_2D10N,_DQ3) ; also on sheet 55
DDR4_DIMM1_DQ46: U8.DC15(IO,_DIFF_TX_2D10N,_DQ3) ; also on sheet 55
DDR4_DIMM1_DQ47: U8.DD14(IO,_DIFF_TX_2D10P,_DQ3) ; also on sheet 55
DDR4_DIMM1_DQ48: U8.CY24(IO,_RZQ_T_2C,_CDR,_DIFF_RX_2C6P,_DQ9) ; also on sheet 55
DDR4_DIMM1_DQ49: U8.DD24(IO,_CLK_T_2C_1P,_DQ9) ; also on sheet 55
DDR4_DIMM1_DQ50: U8.DC25(IO,_CLK_T_2C_1N,_DQ9) ; also on sheet 55
DDR4_DIMM1_DQ51: U8.DA25(IO,_CDR,_DIFF_RX_2C6N,_DQ9) ; also on sheet 55
DDR4_DIMM1_DQ52: U8.CY20(IO,_DIFF_RX_2C4P,_DQ9) ; also on sheet 55
DDR4_DIMM1_DQ53: U8.DC21(IO,_DIFF_TX_2C4N,_DQ9) ; also on sheet 55
DDR4_DIMM1_DQ54: U8.DA21(IO,_DIFF_RX_2C4N,_DQ9) ; also on sheet 55
DDR4_DIMM1_DQ55: U8.DD20(IO,_DIFF_TX_2C4P,_DQ9) ; also on sheet 55
DDR4_DIMM1_DQ56: U8.CY12(IO,_RZQ_T_2D,_CDR,_DIFF_RX_2D6P,_DQ1) ; also on sheet 55
DDR4_DIMM1_DQ57: U8.DC13(IO,_CLK_T_2D_1N,_DIFF_TX_2D6N,_DQ1) ; also on sheet 55
DDR4_DIMM1_DQ58: U8.DA13(IO,_CDR,_DIFF_RX_2D6N,_DQ1) ; also on sheet 55
DDR4_DIMM1_DQ59: U8.DD12(IO,_CLK_T_2D_1P,_DIFF_TX_2D6P,_DQ1) ; also on sheet 55
DDR4_DIMM1_DQ60: U8.DC9(IO,_DIFF_TX_2D4N,_DQ1) ; also on sheet 55
DDR4_DIMM1_DQ61: U8.DA9(IO,_DIFF_RX_2D4N,_DQ1) ; also on sheet 55
DDR4_DIMM1_DQ62: U8.CY8(IO,_DIFF_RX_2D4P,_DQ1) ; also on sheet 55
DDR4_DIMM1_DQ63: U8.DD8(IO,_DIFF_TX_2D4P,_DQ1) ; also on sheet 55
DDR4_DIMM1_DQ64: U8.CW23(IO,_DIFF_TX_2D24N,_DQ7) ; also on sheet 55
DDR4_DIMM1_DQ65: U8.CV22(IO,_DIFF_TX_2D24P,_DQ7) ; also on sheet 55
DDR4_DIMM1_DQ66: U8.CT22(IO,_CDR,_DIFF_RX_2D24P,_DQ7) ; also on sheet 55
DDR4_DIMM1_DQ67: U8.CR23(IO,_CDR,_DIFF_RX_2D24N,_DQ7) ; also on sheet 55
DDR4_DIMM1_DQ68: U8.CR19(IO,_CDR,_DIFF_RX_2D22N,_DQ7) ; also on sheet 55
DDR4_DIMM1_DQ69: U8.CV18(IO,_DIFF_TX_2D22P,_DQ7) ; also on sheet 55
DDR4_DIMM1_DQ70: U8.CW19(IO,_DIFF_TX_2D22N,_DQ7) ; also on sheet 55
DDR4_DIMM1_DQ71: U8.CT18(IO,_CDR,_DIFF_RX_2D22P,_DQ7) ; also on sheet 55
DDR4_DIMM1_DQS_N0: U8.DC29(IO,_DIFF_TX_2C11N,_DQSN11) ; also on sheet 55
DDR4_DIMM1_DQS_N1: U8.DJ19(IO,_DIFF_TX_2C2N,_DQSN8) ; also on sheet 55
DDR4_DIMM1_DQS_N2: U8.DJ7(IO,_DIFF_TX_2D2N,_DQSN0) ; also on sheet 55
DDR4_DIMM1_DQS_N3: U8.DJ13(IO,_DIFF_TX_2D8N,_DQSN2) ; also on sheet 55
DDR4_DIMM1_DQS_N4: U8.DJ25(IO,_DIFF_TX_2C8N,_DQSN10) ; also on sheet 55
DDR4_DIMM1_DQS_N5: U8.DC17(IO,_DIFF_TX_2D11N,_DQSN3) ; also on sheet 55
DDR4_DIMM1_DQS_N6: U8.DC23(IO,_PLL_2C_T_CLKOUT1N,_DIFF_TX_2C5N,_DQSN9) ; also on sheet 55
DDR4_DIMM1_DQS_N7: U8.DC11(IO,_PLL_2D_T_CLKOUT1N,_DIFF_TX_2D5N,_DQSN1) ; also on sheet 55
DDR4_DIMM1_DQS_N8: U8.CW21(IO,_DIFF_TX_2D23N,_DQSN7) ; also on sheet 55
DDR4_DIMM1_DQS_P0: U8.DD28(IO,_DIFF_TX_2C11P,_DQS11) ; also on sheet 55
DDR4_DIMM1_DQS_P1: U8.DH18(IO,_DIFF_TX_2C2P,_DQS8) ; also on sheet 55
DDR4_DIMM1_DQS_P2: U8.DH6(IO,_DIFF_TX_2D2P,_DQS0) ; also on sheet 55
DDR4_DIMM1_DQS_P3: U8.DH12(IO,_DIFF_TX_2D8P,_DQS2) ; also on sheet 55
DDR4_DIMM1_DQS_P4: U8.DH24(IO,_DIFF_TX_2C8P,_DQS10) ; also on sheet 55
DDR4_DIMM1_DQS_P5: U8.DD16(IO,_DIFF_TX_2D11P,_DQS3) ; also on sheet 55
DDR4_DIMM1_DQS_P6: U8.DD22(IO,_PLL_2C_T_CLKOUT1P,_PLL_2C_T_CLKOUT1,_PLL_2C_T_FB1,_DIFF_TX_2C5P,_DQS9) ; also on sheet 55
DDR4_DIMM1_DQS_P7: U8.DD10(IO,_PLL_2D_T_CLKOUT1P,_PLL_2D_T_CLKOUT1,_PLL_2D_T_FB1,_DIFF_TX_2D5P,_DQS1) ; also on sheet 55
DDR4_DIMM1_DQS_P8: U8.CV20(IO,_DIFF_TX_2D23P,_DQS7) ; also on sheet 55
DDR4_DIMM1_ODT0: U8.CP32(IO,_DIFF_TX_2C23P,_DQS15) ; also on sheet 55
DDR4_DIMM1_ODT1: U8.CN33(IO,_DIFF_TX_2C23N,_DQSN15) ; also on sheet 55
DDR4_DIMM1_PAR: U8.CL31(IO,_CDR,_DIFF_RX_2C22N,_DQ15) ; also on sheet 55
DDR4_DIMM1_REFCLK_N: R6908.1 R6931.1 U8.CW29(IO,_CLK_B_2C_1N,_DIFF_TX_2C18N,_DQ13) ; also on sheet 32
DDR4_DIMM1_REFCLK_P: R6908.2 R6930.1 U8.CV28(IO,_CLK_B_2C_1P,_DIFF_TX_2C18P,_DQ13) ; also on sheet 32
DDR4_DIMM1_RESET_N: U8.CN35(IO,_DIFF_TX_2C24N,_DQ15) ; also on sheet 55
DDR4_DIMM1_TDQS_N9: U8.DA29(IO,_DIFF_RX_2C11N,_DQ11) ; also on sheet 55
DDR4_DIMM1_TDQS_N10: U8.DE19(IO,_DIFF_RX_2C2N,_DQ8) ; also on sheet 55
DDR4_DIMM1_TDQS_N11: U8.DE7(IO,_DIFF_RX_2D2N,_DQ0) ; also on sheet 55
DDR4_DIMM1_TDQS_N12: U8.DE13(IO,_PLL_2D_T_CLKOUT0N,_DIFF_RX_2D8N,_DQ2) ; also on sheet 55
DDR4_DIMM1_TDQS_N13: U8.DE25(IO,_PLL_2C_T_CLKOUT0N,_DIFF_RX_2C8N,_DQ10) ; also on sheet 55
DDR4_DIMM1_TDQS_N14: U8.DA17(IO,_DIFF_RX_2D11N,_DQ3) ; also on sheet 55
DDR4_DIMM1_TDQS_N15: U8.DA23(IO,_DIFF_RX_2C5N,_DQ9) ; also on sheet 55
DDR4_DIMM1_TDQS_N16: U8.DA11(IO,_DIFF_RX_2D5N,_DQ1) ; also on sheet 55
DDR4_DIMM1_TDQS_N17: U8.CR21(IO,_DIFF_RX_2D23N,_DQ7) ; also on sheet 55
DDR4_DIMM2_A0: U8.DH38(IO,_DIFF_TX_2F9P,_DQ18) ; also on sheet 56
DDR4_DIMM2_A1: U8.DJ39(IO,_DIFF_TX_2F9N,_DQ18) ; also on sheet 56
DDR4_DIMM2_A2: U8.DF38(IO,_CDR,_DIFF_RX_2F9P,_DQ18) ; also on sheet 56
DDR4_DIMM2_A3: U8.DE39(IO,_CDR,_DIFF_RX_2F9N,_DQ18) ; also on sheet 56
DDR4_DIMM2_A4: U8.DH36(IO,_DIFF_TX_2F8P,_DQS18) ; also on sheet 56
DDR4_DIMM2_A5: U8.DJ37(IO,_DIFF_TX_2F8N,_DQSN18) ; also on sheet 56
DDR4_DIMM2_A6: U8.DF36(IO,_PLL_2F_T_CLKOUT0P,_PLL_2F_T_CLKOUT0,_PLL_2F_T_FB0,_DIFF_RX_2F8P,_DQ18) ; also on sheet 56
DDR4_DIMM2_A7: U8.DE37(IO,_PLL_2F_T_CLKOUT0N,_DIFF_RX_2F8N,_DQ18) ; also on sheet 56
DDR4_DIMM2_A8: U8.DH34(IO,_DIFF_TX_2F7P,_DQ18) ; also on sheet 56
DDR4_DIMM2_A9: U8.DJ35(IO,_DIFF_TX_2F7N,_DQ18) ; also on sheet 56
DDR4_DIMM2_A10: U8.DF34(IO,_CLK_T_2F_0P,_DIFF_RX_2F7P,_DQ18) ; also on sheet 56
DDR4_DIMM2_A11: U8.DE35(IO,_CLK_T_2F_0N,_DIFF_RX_2F7N,_DQ18) ; also on sheet 56
DDR4_DIMM2_A12: U8.DA37(IO,_CDR,_DIFF_RX_2F6N,_DQ17) ; also on sheet 56
DDR4_DIMM2_A13: U8.DD34(IO,_PLL_2F_T_CLKOUT1P,_PLL_2F_T_CLKOUT1,_PLL_2F_T_FB1,_DIFF_TX_2F5P,_DQS17) ; also on sheet 56
DDR4_DIMM2_A14: U8.DC35(IO,_PLL_2F_T_CLKOUT1N,_DIFF_TX_2F5N,_DQSN17) ; also on sheet 56
DDR4_DIMM2_A15: U8.CY34(IO,_DIFF_RX_2F5P,_DQ17) ; also on sheet 56
DDR4_DIMM2_A16: U8.DA35(IO,_DIFF_RX_2F5N,_DQ17) ; also on sheet 56
DDR4_DIMM2_A17: U8.DD32(IO,_DIFF_TX_2F4P,_DQ17) ; also on sheet 56
DDR4_DIMM2_ACT_N: U8.DA43(IO,_CDR,_DIFF_RX_2F12N,_DQ19) ; also on sheet 56
DDR4_DIMM2_ALERT_N: U8.DH28(IO,_DIFF_TX_2F1P,_DQ16) ; also on sheet 56
DDR4_DIMM2_BA0: U8.DC33(IO,_DIFF_TX_2F4N,_DQ17) ; also on sheet 56
DDR4_DIMM2_BA1: U8.CY32(IO,_DIFF_RX_2F4P,_DQ17) ; also on sheet 56
DDR4_DIMM2_BG0: U8.DA33(IO,_DIFF_RX_2F4N,_DQ17) ; also on sheet 56
DDR4_DIMM2_BG1: U8.DD42(IO,_DIFF_TX_2F12P,_DQ19) ; also on sheet 56
DDR4_DIMM2_C0: U8.DH32(IO,_DIFF_TX_2F3P,_DQ16) ; also on sheet 56
DDR4_DIMM2_C1: U8.DJ33(IO,_DIFF_TX_2F3N,_DQ16) ; also on sheet 56
DDR4_DIMM2_CK_N0: U8.DC39(IO,_DIFF_TX_2F10N,_DQ19) ; also on sheet 56
DDR4_DIMM2_CK_N1: U8.DE29(IO,_DIFF_RX_2F1N,_DQ16) ; also on sheet 56
DDR4_DIMM2_CK_P0: U8.DD38(IO,_DIFF_TX_2F10P,_DQ19) ; also on sheet 56
DDR4_DIMM2_CK_P1: U8.DF28(IO,_DIFF_RX_2F1P,_DQ16) ; also on sheet 56
DDR4_DIMM2_CKE0: U8.CY40(IO,_DIFF_RX_2F11P,_DQ19) ; also on sheet 56
DDR4_DIMM2_CKE1: U8.DA41(IO,_DIFF_RX_2F11N,_DQ19) ; also on sheet 56
DDR4_DIMM2_CS_N0: U8.CY42(IO,_CDR,_DIFF_RX_2F12P,_DQ19) ; also on sheet 56
DDR4_DIMM2_CS_N1: U8.CY38(IO,_DIFF_RX_2F10P,_DQ19) ; also on sheet 56
DDR4_DIMM2_DBI_N0: U8.CK44(IO,_DIFF_RX_2F23P,_DQ23) ; also on sheet 56
DDR4_DIMM2_DBI_N1: U8.CY46(IO,_PLL_2E_T_CLKOUT0P,_PLL_2E_T_CLKOUT0,_PLL_2E_T_FB0,_DIFF_RX_2E8P,_DQ26) ; also on sheet 56
DDR4_DIMM2_DBI_N2: U8.CK50(IO,_PLL_2E_B_CLKOUT0P,_PLL_2E_B_CLKOUT0,_PLL_2E_B_FB0,_DIFF_RX_2E20P,_DQ30) ; also on sheet 56
DDR4_DIMM2_DBI_N3: U8.CT44(IO,_PLL_2F_B_CLKOUT0P,_PLL_2F_B_CLKOUT0,_PLL_2F_B_FB0,_DIFF_RX_2F20P,_DQ22) ; also on sheet 56
DDR4_DIMM2_DBI_N4: U8.CT50(IO,_DIFF_RX_2E23P,_DQ31) ; also on sheet 56
DDR4_DIMM2_DBI_N5: U8.CY52(IO,_DIFF_RX_2E2P,_DQ24) ; also on sheet 56
DDR4_DIMM2_DBI_N6: U8.CK38(IO,_DIFF_RX_2F17P,_DQ21) ; also on sheet 56
DDR4_DIMM2_DBI_N7: U8.DF48(IO,_DIFF_RX_2E5P,_DQ25) ; also on sheet 56
DDR4_DIMM2_DBI_N8: U8.CT38(IO,_DIFF_RX_2F14P,_DQ20) ; also on sheet 56
DDR4_DIMM2_DQ0: U8.CK46(IO,_CDR,_DIFF_RX_2F24P,_DQ23) ; also on sheet 56
DDR4_DIMM2_DQ1: U8.CL47(IO,_CDR,_DIFF_RX_2F24N,_DQ23) ; also on sheet 56
DDR4_DIMM2_DQ2: U8.CN47(IO,_DIFF_TX_2F24N,_DQ23) ; also on sheet 56
DDR4_DIMM2_DQ3: U8.CP46(IO,_DIFF_TX_2F24P,_DQ23) ; also on sheet 56
DDR4_DIMM2_DQ4: U8.CL43(IO,_CDR,_DIFF_RX_2F22N,_DQ23) ; also on sheet 56
DDR4_DIMM2_DQ5: U8.CK42(IO,_CDR,_DIFF_RX_2F22P,_DQ23) ; also on sheet 56
DDR4_DIMM2_DQ6: U8.CN43(IO,_DIFF_TX_2F22N,_DQ23) ; also on sheet 56
DDR4_DIMM2_DQ7: U8.CP42(IO,_DIFF_TX_2F22P,_DQ23) ; also on sheet 56
DDR4_DIMM2_DQ8: U8.DA45(IO,_CDR,_DIFF_RX_2E9N,_DQ26) ; also on sheet 56
DDR4_DIMM2_DQ9: U8.DC45(IO,_DIFF_TX_2E9N,_DQ26) ; also on sheet 56
DDR4_DIMM2_DQ10: U8.DD44(IO,_DIFF_TX_2E9P,_DQ26) ; also on sheet 56
DDR4_DIMM2_DQ11: U8.CY44(IO,_CDR,_DIFF_RX_2E9P,_DQ26) ; also on sheet 56
DDR4_DIMM2_DQ12: U8.DA49(IO,_CLK_T_2E_0N,_DIFF_RX_2E7N,_DQ26) ; also on sheet 56
DDR4_DIMM2_DQ13: U8.CY48(IO,_CLK_T_2E_0P,_DIFF_RX_2E7P,_DQ26) ; also on sheet 56
DDR4_DIMM2_DQ14: U8.DD48(IO,_DIFF_TX_2E7P,_DQ26) ; also on sheet 56
DDR4_DIMM2_DQ15: U8.DC49(IO,_DIFF_TX_2E7N,_DQ26) ; also on sheet 56
DDR4_DIMM2_DQ16: U8.CN49(IO,_DIFF_TX_2E21N,_DQ30) ; also on sheet 56
DDR4_DIMM2_DQ17: U8.CP48(IO,_DIFF_TX_2E21P,_DQ30) ; also on sheet 56
DDR4_DIMM2_DQ18: U8.CL49(IO,_CDR,_DIFF_RX_2E21N,_DQ30) ; also on sheet 56
DDR4_DIMM2_DQ19: U8.CK48(IO,_CDR,_DIFF_RX_2E21P,_DQ30) ; also on sheet 56
DDR4_DIMM2_DQ20: U8.CM52(IO,_CLK_B_2E_0P,_CDR,_DIFF_RX_2E19P,_DQ30) ; also on sheet 56
DDR4_DIMM2_DQ21: U8.CT52(IO,_DIFF_TX_2E19P,_DQ30) ; also on sheet 56
DDR4_DIMM2_DQ22: U8.CN53(IO,_CLK_B_2E_0N,_CDR,_DIFF_RX_2E19N,_DQ30) ; also on sheet 56
DDR4_DIMM2_DQ23: U8.CR53(IO,_DIFF_TX_2E19N,_DQ30) ; also on sheet 56
DDR4_DIMM2_DQ24: U8.CR47(IO,_CDR,_DIFF_RX_2F21N,_DQ22) ; also on sheet 56
DDR4_DIMM2_DQ25: U8.CT46(IO,_CDR,_DIFF_RX_2F21P,_DQ22) ; also on sheet 56
DDR4_DIMM2_DQ26: U8.CV46(IO,_DIFF_TX_2F21P,_DQ22) ; also on sheet 56
DDR4_DIMM2_DQ27: U8.CW47(IO,_DIFF_TX_2F21N,_DQ22) ; also on sheet 56
DDR4_DIMM2_DQ28: U8.CW43(IO,_DIFF_TX_2F19N,_DQ22) ; also on sheet 56
DDR4_DIMM2_DQ29: U8.CV42(IO,_DIFF_TX_2F19P,_DQ22) ; also on sheet 56
DDR4_DIMM2_DQ30: U8.CR43(IO,_CLK_B_2F_0N,_CDR,_DIFF_RX_2F19N,_DQ22) ; also on sheet 56
DDR4_DIMM2_DQ31: U8.CT42(IO,_CLK_B_2F_0P,_CDR,_DIFF_RX_2F19P,_DQ22) ; also on sheet 56
DDR4_DIMM2_DQ32: U8.CV48(IO,_DIFF_TX_2E24P,_DQ31) ; also on sheet 56
DDR4_DIMM2_DQ33: U8.CT48(IO,_CDR,_DIFF_RX_2E24P,_DQ31) ; also on sheet 56
DDR4_DIMM2_DQ34: U8.CW49(IO,_DIFF_TX_2E24N,_DQ31) ; also on sheet 56
DDR4_DIMM2_DQ35: U8.CR49(IO,_CDR,_DIFF_RX_2E24N,_DQ31) ; also on sheet 56
DDR4_DIMM2_DQ36: U8.CW53(IO,_DIFF_TX_2E22N,_DQ31) ; also on sheet 56
DDR4_DIMM2_DQ37: U8.CV52(IO,_DIFF_TX_2E22P,_DQ31) ; also on sheet 56
DDR4_DIMM2_DQ38: U8.CW55(IO,_CDR,_DIFF_RX_2E22N,_DQ31) ; also on sheet 56
DDR4_DIMM2_DQ39: U8.CV54(IO,_CDR,_DIFF_RX_2E22P,_DQ31) ; also on sheet 56
DDR4_DIMM2_DQ40: U8.CY50(IO,_CDR,_DIFF_RX_2E3P,_DQ24) ; also on sheet 56
DDR4_DIMM2_DQ41: U8.DC51(IO,_DIFF_TX_2E3N,_DQ24) ; also on sheet 56
DDR4_DIMM2_DQ42: U8.DA51(IO,_CDR,_DIFF_RX_2E3N,_DQ24) ; also on sheet 56
DDR4_DIMM2_DQ43: U8.DD50(IO,_DIFF_TX_2E3P,_DQ24) ; also on sheet 56
DDR4_DIMM2_DQ44: U8.CY54(IO,_DIFF_RX_2E1P,_DQ24) ; also on sheet 56
DDR4_DIMM2_DQ45: U8.DA55(IO,_DIFF_RX_2E1N,_DQ24) ; also on sheet 56
DDR4_DIMM2_DQ46: U8.DD54(IO,_DIFF_TX_2E1P,_DQ24) ; also on sheet 56
DDR4_DIMM2_DQ47: U8.DC55(IO,_DIFF_TX_2E1N,_DQ24) ; also on sheet 56
DDR4_DIMM2_DQ48: U8.CL41(IO,_CDR,_DIFF_RX_2F18N,_DQ21) ; also on sheet 56
DDR4_DIMM2_DQ49: U8.CN41(IO,_CLK_B_2F_1N,_DIFF_TX_2F18N,_DQ21) ; also on sheet 56
DDR4_DIMM2_DQ50: U8.CK40(IO,_RZQ_B_2F,_CDR,_DIFF_RX_2F18P,_DQ21) ; also on sheet 56
DDR4_DIMM2_DQ51: U8.CP40(IO,_CLK_B_2F_1P,_DIFF_TX_2F18P,_DQ21) ; also on sheet 56
DDR4_DIMM2_DQ52: U8.CK36(IO,_CDR,_DIFF_RX_2F16P,_DQ21) ; also on sheet 56
DDR4_DIMM2_DQ53: U8.CN37(IO,_DIFF_TX_2F16N,_DQ21) ; also on sheet 56
DDR4_DIMM2_DQ54: U8.CL37(IO,_CDR,_DIFF_RX_2F16N,_DQ21) ; also on sheet 56
DDR4_DIMM2_DQ55: U8.CP36(IO,_DIFF_TX_2F16P,_DQ21) ; also on sheet 56
DDR4_DIMM2_DQ56: U8.DF46(IO,_RZQ_T_2E,_CDR,_DIFF_RX_2E6P,_DQ25) ; also on sheet 56
DDR4_DIMM2_DQ57: U8.DE47(IO,_CDR,_DIFF_RX_2E6N,_DQ25) ; also on sheet 56
DDR4_DIMM2_DQ58: U8.DH46(IO,_CLK_T_2E_1P,_DIFF_TX_2E6P,_DQ25) ; also on sheet 56
DDR4_DIMM2_DQ59: U8.DJ47(IO,_CLK_T_2E_1N,_DIFF_TX_2E6N,_DQ25) ; also on sheet 56
DDR4_DIMM2_DQ60: U8.DE53(IO,_DIFF_RX_2E4N,_DQ25) ; also on sheet 56
DDR4_DIMM2_DQ61: U8.DF52(IO,_DIFF_RX_2E4P,_DQ25) ; also on sheet 56
DDR4_DIMM2_DQ62: U8.DG51(IO,_DIFF_TX_2E4N,_DQ25) ; also on sheet 56
DDR4_DIMM2_DQ63: U8.DH50(IO,_DIFF_TX_2E4P,_DQ25) ; also on sheet 56
DDR4_DIMM2_DQ64: U8.CW41(IO,_DIFF_TX_2F15N,_DQ20) ; also on sheet 56
DDR4_DIMM2_DQ65: U8.CV40(IO,_DIFF_TX_2F15P,_DQ20) ; also on sheet 56
DDR4_DIMM2_DQ66: U8.CR41(IO,_CDR,_DIFF_RX_2F15N,_DQ20) ; also on sheet 56
DDR4_DIMM2_DQ67: U8.CT40(IO,_CDR,_DIFF_RX_2F15P,_DQ20) ; also on sheet 56
DDR4_DIMM2_DQ68: U8.CR37(IO,_CDR,_DIFF_RX_2F13N,_DQ20) ; also on sheet 56
DDR4_DIMM2_DQ69: U8.CV36(IO,_DIFF_TX_2F13P,_DQ20) ; also on sheet 56
DDR4_DIMM2_DQ70: U8.CW37(IO,_DIFF_TX_2F13N,_DQ20) ; also on sheet 56
DDR4_DIMM2_DQ71: U8.CT36(IO,_CDR,_DIFF_RX_2F13P,_DQ20) ; also on sheet 56
DDR4_DIMM2_DQS_N0: U8.CN45(IO,_DIFF_TX_2F23N,_DQSN23) ; also on sheet 56
DDR4_DIMM2_DQS_N1: U8.DC47(IO,_DIFF_TX_2E8N,_DQSN26) ; also on sheet 56
DDR4_DIMM2_DQS_N2: U8.CN51(IO,_DIFF_TX_2E20N,_DQSN30) ; also on sheet 56
DDR4_DIMM2_DQS_N3: U8.CW45(IO,_DIFF_TX_2F20N,_DQSN22) ; also on sheet 56
DDR4_DIMM2_DQS_N4: U8.CW51(IO,_DIFF_TX_2E23N,_DQSN31) ; also on sheet 56
DDR4_DIMM2_DQS_N5: U8.DC53(IO,_DIFF_TX_2E2N,_DQSN24) ; also on sheet 56
DDR4_DIMM2_DQS_N6: U8.CN39(IO,_PLL_2F_B_CLKOUT1N,_DIFF_TX_2F17N,_DQSN21) ; also on sheet 56
DDR4_DIMM2_DQS_N7: U8.DJ49(IO,_PLL_2E_T_CLKOUT1N,_DIFF_TX_2E5N,_DQSN25) ; also on sheet 56
DDR4_DIMM2_DQS_N8: U8.CW39(IO,_DIFF_TX_2F14N,_DQSN20) ; also on sheet 56
DDR4_DIMM2_DQS_P0: U8.CP44(IO,_DIFF_TX_2F23P,_DQS23) ; also on sheet 56
DDR4_DIMM2_DQS_P1: U8.DD46(IO,_DIFF_TX_2E8P,_DQS26) ; also on sheet 56
DDR4_DIMM2_DQS_P2: U8.CP50(IO,_DIFF_TX_2E20P,_DQS30) ; also on sheet 56
DDR4_DIMM2_DQS_P3: U8.CV44(IO,_DIFF_TX_2F20P,_DQS22) ; also on sheet 56
DDR4_DIMM2_DQS_P4: U8.CV50(IO,_DIFF_TX_2E23P,_DQS31) ; also on sheet 56
DDR4_DIMM2_DQS_P5: U8.DD52(IO,_DIFF_TX_2E2P,_DQS24) ; also on sheet 56
DDR4_DIMM2_DQS_P6: U8.CP38(IO,_PLL_2F_B_CLKOUT1P,_PLL_2F_B_CLKOUT1,_PLL_2F_B_FB1,_DIFF_TX_2F17P,_DQS21) ; also on sheet 56
DDR4_DIMM2_DQS_P7: U8.DH48(IO,_PLL_2E_T_CLKOUT1P,_PLL_2E_T_CLKOUT1,_PLL_2E_T_FB1,_DIFF_TX_2E5P,_DQS25) ; also on sheet 56
DDR4_DIMM2_DQS_P8: U8.CV38(IO,_DIFF_TX_2F14P,_DQS20) ; also on sheet 56
DDR4_DIMM2_ODT0: U8.DD40(IO,_DIFF_TX_2F11P,_DQS19) ; also on sheet 56
DDR4_DIMM2_ODT1: U8.DC41(IO,_DIFF_TX_2F11N,_DQSN19) ; also on sheet 56
DDR4_DIMM2_PAR: U8.DA39(IO,_DIFF_RX_2F10N,_DQ19) ; also on sheet 56
DDR4_DIMM2_REFCLK_N: R6909.2 R6933.1 U8.DC37(IO,_CLK_T_2F_1N,_DIFF_TX_2F6N,_DQ17) ; also on sheet 32
DDR4_DIMM2_REFCLK_P: R6909.1 R6932.1 U8.DD36(IO,_CLK_T_2F_1P,_DIFF_TX_2F6P,_DQ17) ; also on sheet 32
DDR4_DIMM2_RESET_N: U8.DC43(IO,_DIFF_TX_2F12N,_DQ19) ; also on sheet 56
DDR4_DIMM2_TDQS_N9: U8.CL45(IO,_DIFF_RX_2F23N,_DQ23) ; also on sheet 56
DDR4_DIMM2_TDQS_N10: U8.DA47(IO,_PLL_2E_T_CLKOUT0N,_DIFF_RX_2E8N,_DQ26) ; also on sheet 56
DDR4_DIMM2_TDQS_N11: U8.CL51(IO,_PLL_2E_B_CLKOUT0N,_DIFF_RX_2E20N,_DQ30) ; also on sheet 56
DDR4_DIMM2_TDQS_N12: U8.CR45(IO,_PLL_2F_B_CLKOUT0N,_DIFF_RX_2F20N,_DQ22) ; also on sheet 56
DDR4_DIMM2_TDQS_N13: U8.CR51(IO,_DIFF_RX_2E23N,_DQ31) ; also on sheet 56
DDR4_DIMM2_TDQS_N14: U8.DA53(IO,_DIFF_RX_2E2N,_DQ24) ; also on sheet 56
DDR4_DIMM2_TDQS_N15: U8.CL39(IO,_DIFF_RX_2F17N,_DQ21) ; also on sheet 56
DDR4_DIMM2_TDQS_N16: U8.DE49(IO,_DIFF_RX_2E5N,_DQ25) ; also on sheet 56
DDR4_DIMM2_TDQS_N17: U8.CR39(IO,_DIFF_RX_2F14N,_DQ20) ; also on sheet 56
F_CLK_FPGA_100M_N: R6841.1 R6842.2 R6929.1 U8.CL19(IO,_CLK_B_2D_0N,_CDR,_DIFF_RX_2D19N,_DQ6)
F_CLK_FPGA_100M_P: R6840.1 R6843.2 R6929.2 U8.CK18(IO,_CLK_B_2D_0P,_CDR,_DIFF_RX_2D19P,_DQ6)
FPGA_1V8_ASx4_CLK: R103.2 R769.1 U9.B2(C)
FPGA_1V8_ASx4_CS0n_MSEL0: R105.1 U8.CC45(SDM_IO5,_AS_nCSO0,_MSEL0_QSPI_SS0__SDMMC_CCLK) U9.C2(S#)
FPGA_1V8_ASx4_D0: U8.CG45(SDM_IO4,_AVSTx8_DATA1,_AS_DATA0_QSPI_IO0__SDMMC_CMD) U9.D3(DQ0)
FPGA_1V8_ASx4_D1: U8.CA45(SDM_IO1,_AVSTx8_DATA2,_AS_DATA1_QSPI_IO1__SDMMC_DATA1) U9.D2(DQ1)
FPGA_1V8_ASx4_D2: R772.1 U8.CF46(SDM_IO3,_AVSTx8_DATA3,_AS_DATA2_QSPI_IO2_WPN__SDMMC_DATA2) U9.C4(W#/DQ2)
FPGA_1V8_ASx4_D3: R773.1 U8.CH46(SDM_IO6,_AVSTx8_DATA4,_AS_DATA3_QSPI_IO3_HOLD__SDMMC_DATA3) U9.D4(DQ3)
FPGA_1V8_ASx4_RESETN: R106.1 U8.CB44(SDM_IO15,_AVSTx8_DATA6,_AS_nRST_SDMMC_DATA6) U9.A4(RESET#/DNU)
FPGA_1V8_CATTRIPn: R764.1 U8.CD48(SDM_IO12,_PWRMGT_SDA,_PWRMGT_ALERT_PWRMGT_ALERT) ; also on sheet 10
FPGA_1V8_CONF_DONE: U8.CH44(SDM_IO16_PWRMGT_SDA_STATUS1__CONF_DONE) ; also on sheet 10 36
FPGA_1V8_CVP_CONF_DONE: U8.BY46(SDM_IO14,_AVSTx8_CLK,_PWRMGT_SCL_I2C_PWRMGT_SCL) ; also on sheet 10
FPGA_1V8_INIT_DONE: R762.2 U8.CA43(SDM_IO13,_AVSTx8_DATA5_SDMMC_DATA5) ; also on sheet 10
FPGA_1V8_JTAG_TCK: R761.2 U8.CF44(TCK) ; also on sheet 10
FPGA_1V8_JTAG_TDI: R760.1 U8.CC43(TDI) ; also on sheet 10
FPGA_1V8_JTAG_TDO: U8.CC49(TDO) ; also on sheet 10
FPGA_1V8_JTAG_TMS: R759.1 U8.CE43(TMS) ; also on sheet 10
FPGA_1V8_MSEL1: R97.1 SW3.1(A1) U8.CR55(SDM_IO7,_AS_nCSO2,_MSEL1_QSPI_SS2) ; also on sheet 10
FPGA_1V8_MSEL2: R98.1 SW3.2(A2) U8.CF48(SDM_IO9,_AS_nCSO1,_MSEL2,_PWRMGT_ALERT_QSPI_SS1__SDMMC_PWR_ENA) ; also on sheet 10
FPGA_1V8_NCONFIG: R96.1 U8.CC47(NRST__NCONFIG) ; also on sheet 10
FPGA_1V8_NSTATUS: R95.1 U8.CE47(STATUS0__NSTATUS) ; also on sheet 10
FPGA_1V8_SVID_SCL: U8.CG47(SDM_IO0,_PWRMGT_SCL,_PWRMGT_ALERT_STATUS2__INIT_DONE) ; also on sheet 35
FPGA_1V8_SVID_SDA: U8.CB46(SDM_IO11,_AVSTx8_VALID,_PWRMGT_SDA_I2C_PWRMGT_SDA) ; also on sheet 35
FPGA_OSC_CLK1: R107.2 U8.CB42(OSC_CLK_1)
FPGA_TEMP0An: U8.CD50(TEMPDIODEA0n) ; also on sheet 34
FPGA_TEMP0Ap: U8.CE49(TEMPDIODEA0p) ; also on sheet 34
FPGA_VCCIO_SDM_HPS: C101.2 R95.2 R96.2 R97.2 R98.2 R740.2 R759.2 R760.2 R763.2 R764.2 R765.2 U10.1(EN) U10.4(VDD) ; also on sheet 23 28 33 35 39 52 53
HPS_COLD_RESETn: R763.1 U8.CE45(SDM_IO10,_AVSTx8_DATA7_SDMMC_DATA7) ; also on sheet 10
HPS_JTAG_BYPASS: R765.1 SW3.4(A4) ; also on sheet 10
MAX_1V8: C99.2 C100.2 R105.2 R106.2 R772.2 R773.2 U9.B4(VCC) ; also on sheet 9 10 34 58
N226751: R99.2 SW3.8(B1)
N226787: R100.2 SW3.7(B2)
N226815: R101.2 SW3.6(B3)
N226847: R102.2 SW3.5(B4)
N227760: R103.1 U8.CH48(SDM_IO2,_AVSTx8_DATA0,_AS_CLK_QSPI_CLK__SDMMC_DATA0)
N465030: R104.2 U8.CE51(RREF_SDM)
N1918614: R107.1 U10.3(OUT)

Not connected (* = marked no-connect by the designer): U8 BY44(SDM_IO8,_AVSTx8_READY,_AS_nCSO3_QSPI_SS3__SDMMC_DATA4)* CJ53(DNU)* CK12(IO,_CDR,_DIFF_RX_2D13P,_DQ4)* CK14(IO,_DIFF_RX_2D14P,_DQ4)* CK16(IO,_CDR,_DIFF_RX_2D15P,_DQ4)* CK20(IO,_PLL_2D_B_CLKOUT0P,_PLL_2D_B_CLKOUT0,_PLL_2D_B_FB0,_DIFF_RX_2D20P,_DQ6)* CK22(IO,_CDR,_DIFF_RX_2D21P,_DQ6)* CK26(IO,_DIFF_RX_2C14P,_DQ12)* CK28(IO,_CDR,_DIFF_RX_2C15P,_DQ12)* CK52(DNU)* CL13(IO,_CDR,_DIFF_RX_2D13N,_DQ4)* CL15(IO,_DIFF_RX_2D14N,_DQ4)* CL17(IO,_CDR,_DIFF_RX_2D15N,_DQ4)* CL21(IO,_PLL_2D_B_CLKOUT0N,_DIFF_RX_2D20N,_DQ6)* CL23(IO,_CDR,_DIFF_RX_2D21N,_DQ6)* CL27(IO,_DIFF_RX_2C14N,_DQ12)* CL29(IO,_CDR,_DIFF_RX_2C15N,_DQ12)* CN13(IO,_DIFF_TX_2D13N,_DQ4)* CN15(IO,_DIFF_TX_2D14N,_DQSN4)* CN17(IO,_DIFF_TX_2D15N,_DQ4)* CN19(IO,_DIFF_TX_2D19N,_DQ6)* CN21(IO,_DIFF_TX_2D20N,_DQSN6)* CN23(IO,_DIFF_TX_2D21N,_DQ6)* CN25(IO,_DIFF_TX_2C13N,_DQ12)* CN27(IO,_DIFF_TX_2C14N,_DQSN12)* CP12(IO,_DIFF_TX_2D13P,_DQ4)* CP14(IO,_DIFF_TX_2D14P,_DQS4)* CP16(IO,_DIFF_TX_2D15P,_DQ4)* CP18(IO,_DIFF_TX_2D19P,_DQ6)* CP20(IO,_DIFF_TX_2D20P,_DQS6)* CP22(IO,_DIFF_TX_2D21P,_DQ6)* CP26(IO,_DIFF_TX_2C14P,_DQS12)* CR13(IO,_CDR,_DIFF_RX_2D16N,_DQ5)* CR15(IO,_DIFF_RX_2D17N,_DQ5)* CR17(IO,_CDR,_DIFF_RX_2D18N,_DQ5)* CT12(IO,_CDR,_DIFF_RX_2D16P,_DQ5)* CT14(IO,_DIFF_RX_2D17P,_DQ5)* CV12(IO,_DIFF_TX_2D16P,_DQ5)* CV14(IO,_PLL_2D_B_CLKOUT1P,_PLL_2D_B_CLKOUT1,_PLL_2D_B_FB1,_DIFF_TX_2D17P,_DQS5)* CV16(IO,_CLK_B_2D_1P,_DIFF_TX_2D18P,_DQ5)* CW13(IO,_DIFF_TX_2D16N,_DQ5)* CW15(IO,_PLL_2D_B_CLKOUT1N,_DIFF_TX_2D17N,_DQSN5)* CW17(IO,_CLK_B_2D_1N,_DIFF_TX_2D18N,_DQ5)* DE31(IO,_DIFF_RX_2F2N,_DQ16)* DE33(IO,_CDR,_DIFF_RX_2F3N,_DQ16)* DE41(IO,_CDR,_DIFF_RX_2E12N,_DQ27)* DE43(IO,_DIFF_RX_2E11N,_DQ27)* DE45(IO,_DIFF_RX_2E10N,_DQ27)* DF30(IO,_DIFF_RX_2F2P,_DQ16)* DF32(IO,_CDR,_DIFF_RX_2F3P,_DQ16)* DF40(IO,_CDR,_DIFF_RX_2E12P,_DQ27)* DF42(IO,_DIFF_RX_2E11P,_DQ27)* DF44(IO,_DIFF_RX_2E10P,_DQ27)* DH30(IO,_DIFF_TX_2F2P,_DQS16)* DH40(IO,_DIFF_TX_2E12P,_DQ27)* DH42(IO,_DIFF_TX_2E11P,_DQS27)* DH44(IO,_DIFF_TX_2E10P,_DQ27)* DJ29(IO,_DIFF_TX_2F1N,_DQ16)* DJ31(IO,_DIFF_TX_2F2N,_DQSN16)* DJ41(IO,_DIFF_TX_2E12N,_DQ27)* DJ43(IO,_DIFF_TX_2E11N,_DQSN27)* DJ45(IO,_DIFF_TX_2E10N,_DQ27)*; U9 A2(DNU1)* A3(DNU2)* A5(DNU3)* B1(DNU4)* B5(DNU5)* C1(DNU6)* C3(DNU7)* C5(DNU8)* D1(DNU9)* D5(DNU10)* E1(DNU11)* E2(DNU12)* E3(DNU13)* E4(DNU14)* E5(DNU15)*

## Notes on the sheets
sheet 11
- 20K internal pull-down on OSC_CLK1
- 0.164V when SW3 closed
- Pull-up on PG38
- Close = 0,  Open = 1
- For SDM Pins:
  Vil = 0.35 x VCCIO_SDM = 0.63V
  Vih = 0.65 x VCCIO_SDM = 1.17V
  Vol = 0.4V
  Voh = VCCIO_SDM - 0.4V = 1.4V
- Config Mode     MSEL2     MSEL1     MSEL0
    JTAG                 1                 1                1
   AVST x16          1                 0                1
  AS x4 Fast          0                 0                1
  (CVP)
  AS x4 Norm        0                 1                1
- MSELx = 0.164V when SW3 closed
- Pull-up on PG10
- Pull-up on PG38
- CATTRIP = 0 if FPGA Die Temp => 120C
- Route as a diff pair and avoid other nearby signals
- SDM
- ASx4 QSPI Flash
- 2Gbit Flash
- 1.7-2.0V
  Absmax = 4V
- 125MHz LVCMOS
- 2Gb Serial Flash
sheet 12
- Byte1: 8-15
- Byte6: 48-55
- Place near RZQ pin
- Byte4: 32-39
- Byte0: 0-7
- BANK 2C available in both FM86, FM76
- External termination for tuning since OCT +/-40ohm accuracy.
  OCT should be turned off when external termination is used
sheet 13
- Byte2: 16-23
- Byte7: 56-63
- Place near RZQ pin
- Byte3: 24-31
- Place near FPGA Clock input pins
- Byte5: 40-47
- ECC: 64-71
- BANK 2D available in both FM86, FM76
- External termination for tuning since OCT +/-40ohm accuracy.
  OCT should be turned off when external termination is used
sheet 14
- DIMM2 not available in FM76 Devkit version since
  Bank2E does not migrate from FM86 --> FM76
- (FM76: NC)
- (FM76: NC)
- (FM76: NC)
- (FM76: NC)
- (FM76: NC)
- (FM76: NC)
- (FM76: NC)
- (FM76: NC)
- (FM76: NC)
- (FM76: NC)
- (FM76: NC)
- (FM76: NC)
- (FM76: NC)
- 40-47
- (FM76: NC)
- (FM76: NC)
- (FM76: NC)
- (FM76: NC)
- (FM76: NC)
- (FM76: NC)
- (FM76: NC)
- (FM76: NC)
- (FM76: NC)
- (FM76: NC)
- (FM76: NC)
- (FM76: NC)
- (FM76: NC)
- (FM76: NC)
- (FM76: NC)
- (FM76: NC)
- (FM76: NC)
- (FM76: NC)
- (FM76: NC)
- (FM76: NC)
- (FM76: NC)
- (FM76: NC)
- (FM76: NC)
- (FM76: NC)
- 56-63
- (FM76: NC)
- (FM76: NC)
- 16-23
- (FM76: NC)
- (FM76: NC)
- (FM76: NC)
- (FM76: NC)
- (FM76: NC)
- (FM76: NC)
- (FM76: NC)
- (FM76: NC)
- (FM76: NC)
- (FM76: NC)
- (FM76: NC)
- (FM76: NC)
- (FM76: NC)
- (FM76: NC)
- (FM76: NC)
- (FM76: NC)
- (FM76: NC)
- (FM76: NC)
- (FM76: NC)
- (FM76: NC)
- (FM76: NC)
- 8-15
- 32-39
- (FM76: NC)
- (FM76: NC)
- (FM76: NC)
- (FM76: NC)
- (FM76: NC)
- (FM76: NC)
- (FM76: NC)
- (FM76: NC)
- (FM76: NC)
- (FM76: NC)
- (FM76: NC)
- (FM76: NC)
- BANK 2E available only in FM86, not FM76
sheet 15
- DIMM2 not available in FM76 Devkit version
- 64-71
- 48-55
- Place near RZQ pin
- 24-31
- 0-7
- BANK 2F available in both FM86, FM76
- External termination for tuning since OCT +/-40ohm accuracy.
  OCT should be turned off when external termination is used
